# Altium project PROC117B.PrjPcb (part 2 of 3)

## Sheet PROC117B_Temp_Current_sensors_EPROM.SchDoc: TEMP_CURRENT_SENSORS_EEPROM
size 431 x 279 mm; Date: Not shown in title block; ApprovedBy: Not shown in title block; CheckedBy: Not shown in title block; Author: Not shown in title block; CompanyName: Not shown in title block; DrawnBy: Mistral; Engineer: Not shown in title block; Organization: Not shown in title block; Address1: Not shown in title block; Address2: Not shown in title block; Address3: Not shown in title block; Address4: Not shown in title block; DocumentNumber: 8; Revision: Use project parameter SCH_Rev; SheetNumber: 8; SheetTotal: 16; PageSetup: Record=PageOptions¦CenterHorizontal=True¦CenterVertical=True¦PrintScale=1.00¦XCorrection=1.00¦YCorrection=1.00¦PrintKind=0¦BorderSize=5000000¦LeftOffset=0¦BottomOffset=0¦Orientation=2¦PaperLength=1000¦PaperWidth=1000¦Scale=100¦PaperSource=15¦PrintQuality=600¦MediaType=1¦DitherType=10¦PaperKind=Letter¦PrintScaleMode=1
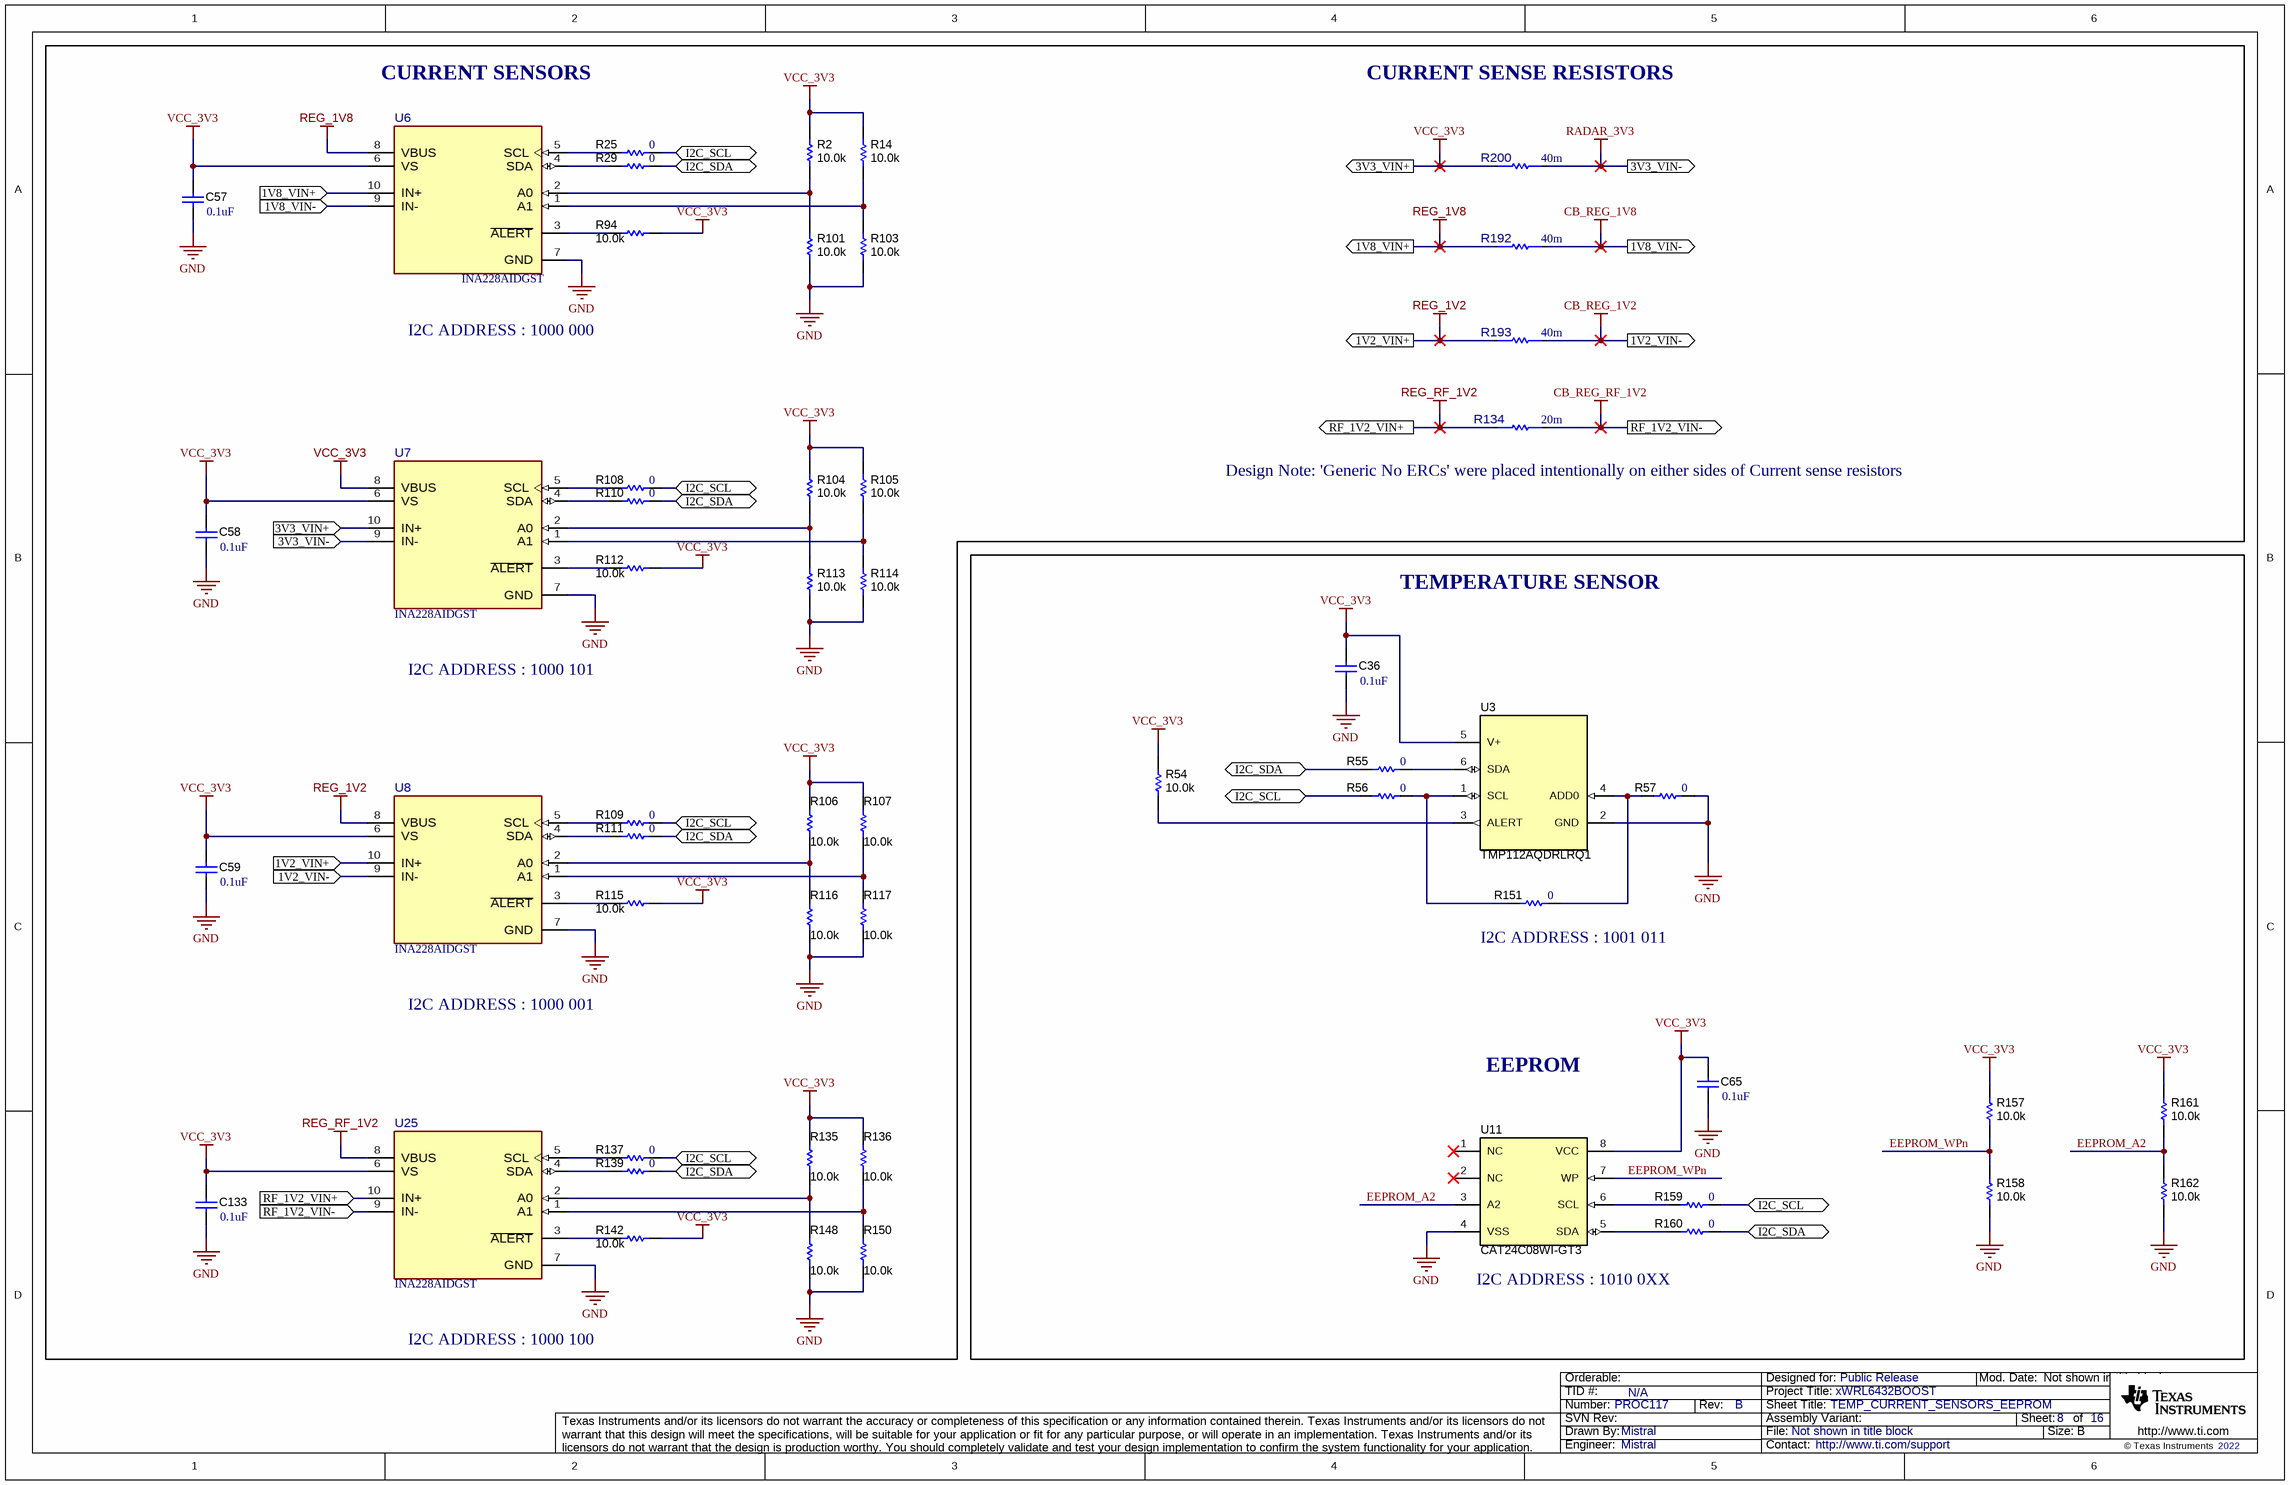
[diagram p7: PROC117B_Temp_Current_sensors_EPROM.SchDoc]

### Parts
C36  ValueDisplayed: 0.1uF  [0402]  (hidden comment: GCM155R71H104KE02D)
C57  ValueDisplayed: 0.1uF  [0402]  (hidden comment: GCM155R71H104KE02D)
C58  ValueDisplayed: 0.1uF  [0402]  (hidden comment: GCM155R71H104KE02D)
C59  ValueDisplayed: 0.1uF  [0402]  (hidden comment: GCM155R71H104KE02D)
C65  ValueDisplayed: 0.1uF  [0402]  (hidden comment: GCM155R71H104KE02D)
C133  ValueDisplayed: 0.1uF  [0402]  (hidden comment: GCM155R71H104KE02D)
R2  ValueDisplayed: 10.0k  [0402L]  (hidden comment: CRCW040210K0FKED)
R14  ValueDisplayed: 10.0k  [0402L]  (hidden comment: CRCW040210K0FKED)
R25  ValueDisplayed: 0  [0201]  (hidden comment: CRCW02010000Z0ED)
R29  ValueDisplayed: 0  [0201]  (hidden comment: CRCW02010000Z0ED)
R54  ValueDisplayed: 10.0k  [0402L]  (hidden comment: CRCW040210K0FKED)
R55  ValueDisplayed: 0  [0201]  (hidden comment: CRCW02010000Z0ED)
R56  ValueDisplayed: 0  [0201]  (hidden comment: CRCW02010000Z0ED)
R57  Res_ohm: 0  [0402]  (hidden comment: CRCW04020000Z0ED)
R94  ValueDisplayed: 10.0k  [0402L]  (hidden comment: CRCW040210K0FKED)
R101  ValueDisplayed: 10.0k  [0402L]  (hidden comment: CRCW040210K0FKED)
R103  ValueDisplayed: 10.0k  [0402L]  (hidden comment: CRCW040210K0FKED)
R104  ValueDisplayed: 10.0k  [0402L]  (hidden comment: CRCW040210K0FKED)
R105  ValueDisplayed: 10.0k  [0402L]  (hidden comment: CRCW040210K0FKED)
R106  ValueDisplayed: 10.0k  [0402L]  (hidden comment: CRCW040210K0FKED)
R107  ValueDisplayed: 10.0k  [0402L]  (hidden comment: CRCW040210K0FKED)
R108  ValueDisplayed: 0  [0201]  (hidden comment: CRCW02010000Z0ED)
R109  ValueDisplayed: 0  [0201]  (hidden comment: CRCW02010000Z0ED)
R110  ValueDisplayed: 0  [0201]  (hidden comment: CRCW02010000Z0ED)
R111  ValueDisplayed: 0  [0201]  (hidden comment: CRCW02010000Z0ED)
R112  ValueDisplayed: 10.0k  [0402L]  (hidden comment: CRCW040210K0FKED)
R113  ValueDisplayed: 10.0k  [0402L]  (hidden comment: CRCW040210K0FKED)
R114  ValueDisplayed: 10.0k  [0402L]  (hidden comment: CRCW040210K0FKED)
R115  ValueDisplayed: 10.0k  [0402L]  (hidden comment: CRCW040210K0FKED)
R116  ValueDisplayed: 10.0k  [0402L]  (hidden comment: CRCW040210K0FKED)
R117  ValueDisplayed: 10.0k  [0402L]  (hidden comment: CRCW040210K0FKED)
R134  value 20m  [FP-WSL1206R0200FEB_1206-MFG]  (hidden comment: WSL1206R0200FEB)
R135  ValueDisplayed: 10.0k  [0402L]  (hidden comment: CRCW040210K0FKED)
R136  ValueDisplayed: 10.0k  [0402L]  (hidden comment: CRCW040210K0FKED)
R137  ValueDisplayed: 0  [0201]  (hidden comment: CRCW02010000Z0ED)
R139  ValueDisplayed: 0  [0201]  (hidden comment: CRCW02010000Z0ED)
R142  ValueDisplayed: 10.0k  [0402L]  (hidden comment: CRCW040210K0FKED)
R148  ValueDisplayed: 10.0k  [0402L]  (hidden comment: CRCW040210K0FKED)
R150  ValueDisplayed: 10.0k  [0402L]  (hidden comment: CRCW040210K0FKED)
R151  Res_ohm: 0  [0402]  (hidden comment: CRCW04020000Z0ED)
R157  ValueDisplayed: 10.0k  [0402L]  (hidden comment: CRCW040210K0FKED)
R158  ValueDisplayed: 10.0k  [0402L]  (hidden comment: CRCW040210K0FKED)
R159  ValueDisplayed: 0  [0201]  (hidden comment: CRCW02010000Z0ED)
R160  ValueDisplayed: 0  [0201]  (hidden comment: CRCW02010000Z0ED)
R161  ValueDisplayed: 10.0k  [0402L]  (hidden comment: CRCW040210K0FKED)
R162  ValueDisplayed: 10.0k  [0402L]  (hidden comment: CRCW040210K0FKED)
R192  value 40m  [FP-WSL1206R0400FEB_1206-MFG]  (hidden comment: WSL1206R0400FEB)
R193  value 40m  [FP-WSL1206R0400FEB_1206-MFG]  (hidden comment: WSL1206R0400FEB)
R200  value 40m  [FP-WSL1206R0400FEB_1206-MFG]  (hidden comment: WSL1206R0400FEB)
U3  TMP112AQDRLRQ1  [DRL0006A]
U6  INA228AIDGST  [DGS0010A-MFG]
U7  INA228AIDGST  [DGS0010A-MFG]
U8  INA228AIDGST  [DGS0010A-MFG]
U11  CAT24C08WI-GT3  [SOIC-8]
U25  INA228AIDGST  [DGS0010A-MFG]

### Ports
1V2_VIN+ (in), 1V2_VIN+ (out), 1V2_VIN- (in), 1V2_VIN- (out), 1V8_VIN+ (in), 1V8_VIN+ (out), 1V8_VIN- (in), 1V8_VIN- (out), 3V3_VIN+ (in), 3V3_VIN+ (out), 3V3_VIN- (in), 3V3_VIN- (out), I2C_SCL (bidir), I2C_SDA (bidir), RF_1V2_VIN+ (in), RF_1V2_VIN+ (out), RF_1V2_VIN- (in), RF_1V2_VIN- (out)

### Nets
CB_REG_1V2: R193.2 U8.9(IN-) ; port 1V2_VIN-
CB_REG_1V8: R192.2 U6.9(IN-) ; port 1V8_VIN-
CB_REG_RF_1V2: R134.2 U25.9(IN-) ; port RF_1V2_VIN-
GND: C36.2 C57.2 C58.2 C59.2 C65.2 C133.2 R57.2 R101.1 R103.1 R113.1 R114.1 R116.1 R117.1 R148.1 R150.1 R158.1 R162.1 U3.2(GND) U6.7(GND) U7.7(GND) U8.7(GND) U11.4(VSS) U25.7(GND)
RADAR_3V3: R200.2 U7.9(IN-) ; port 3V3_VIN-
REG_1V2: R193.1 U8.8(VBUS) U8.10(IN+) ; port 1V2_VIN+
REG_1V8: R192.1 U6.8(VBUS) U6.10(IN+) ; port 1V8_VIN+
REG_RF_1V2: R134.1 U25.8(VBUS) U25.10(IN+) ; port RF_1V2_VIN+
VCC_3V3: C36.1 C57.1 C58.1 C59.1 C65.1 C133.1 R2.2 R14.2 R54.2 R94.1 R104.2 R105.2 R106.2 R107.2 R112.1 R115.1 R135.2 R136.2 R142.1 R157.2 R161.2 R200.1 U3.5(V+) U6.6(VS) U7.6(VS) U7.8(VBUS) U7.10(IN+) U8.6(VS) U11.8(VCC) U25.6(VS) ; port 3V3_VIN+
EEPROM_A2: R161.1 R162.2 U11.3(A2)
EEPROM_WPn: R157.1 R158.2 U11.7(WP)
I2C_SCL: R25.2 R56.1 R108.2 R109.2 R137.2 R159.2 ; port I2C_SCL
I2C_SDA: R29.2 R55.1 R110.2 R111.2 R139.2 R160.2 ; port I2C_SDA
NetR2_1: R2.1 R101.2 U6.2(A0)
NetR14_1: R14.1 R103.2 U6.1(A1)
NetR25_1: R25.1 U6.5(SCL)
NetR29_1: R29.1 U6.4(SDA)
NetR54_1: R54.1 U3.3(ALERT)
NetR55_2: R55.2 U3.6(SDA)
NetR56_2: R56.2 R151.1 U3.1(SCL)
NetR57_1: R57.1 R151.2 U3.4(ADD0)
NetR94_2: R94.2 U6.3(~{ALERT})
NetR104_1: R104.1 R113.2 U7.2(A0)
NetR105_1: R105.1 R114.2 U7.1(A1)
NetR106_1: R106.1 R116.2 U8.2(A0)
NetR107_1: R107.1 R117.2 U8.1(A1)
NetR108_1: R108.1 U7.5(SCL)
NetR109_1: R109.1 U8.5(SCL)
NetR110_1: R110.1 U7.4(SDA)
NetR111_1: R111.1 U8.4(SDA)
NetR112_2: R112.2 U7.3(~{ALERT})
NetR115_2: R115.2 U8.3(~{ALERT})
NetR135_1: R135.1 R148.2 U25.2(A0)
NetR136_1: R136.1 R150.2 U25.1(A1)
NetR137_1: R137.1 U25.5(SCL)
NetR139_1: R139.1 U25.4(SDA)
NetR142_2: R142.2 U25.3(~{ALERT})
NetR159_1: R159.1 U11.6(SCL)
NetR160_1: R160.1 U11.5(SDA)

Not connected (* = marked no-connect by the designer): U11 1(NC)* 2(NC)*

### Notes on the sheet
- CURRENT SENSORS
- CURRENT SENSE RESISTORS
- I2C ADDRESS : 1000 000
- (near R134) Design Note: 'Generic No ERCs' were placed intentionally on either sides of Current sense resistors
- TEMPERATURE SENSOR
- I2C ADDRESS : 1000 101
- (near R151) I2C ADDRESS : 1001 011
- I2C ADDRESS : 1000 001
- EEPROM
- I2C ADDRESS : 1010 0XX
- I2C ADDRESS : 1000 100

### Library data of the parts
C36 C57-C59 C65 C133 = CMP-0006356-2: CAP, CERM, 0.1 uF, 50 V, +/- 10%, X7R, AEC-Q200 Grade 1, 0402; Manufacturer: MuRata; TaMin_C: -55°C; Polarized: N; SizeAreaWB_mm2: 3; Value1: Unknown; U/M: EA; Value: 0.1uF; TaMax_C: 125°C; SizeZ_mm: 0.6; SizeX_mm: 1; SizeY_mm: 0.5; Value2: 50V; AEC Qualified: Y; Cap_F: 100nF; AEC Category: Q200
R2 R14 R54 R94 R101 R103-R107 R112-R117 R135 R136 R142 R148 R150 R157 R158 R161 R162 = CMP-0025958-3: RES, 10.0 k, 1%, 0.063 W, AEC-Q200 Grade 0, 0402; Manufacturer: Vishay-Dale; Power_W: 63mW; TempCo: 100 ppm/C; Value_Code: 10k0; Value: 10.0k; EIA_Code: E96; Res_ohm: 10k; SizeX_mm: 1; SizeY_mm: 0.5; SizeZ_mm: 0.6; Value2: 0.063W; AEC Qualified: Y; VDC_V: 50V; AEC Category: Q200; AEC Grade: 0
R25 R29 R55 R56 R108-R111 R137 R139 R159 R160 = CMP-0027008-4: RES, 0, 5%, 0.05 W, 0201; Manufacturer: Vishay-Dale; Power_W: 50mW; TempCo: ppm/C; Value_Code: 0000; Value: 0; EIA_Code: E24; SizeX_mm: 0.6; SizeY_mm: 0.3; SizeZ_mm: 0.26; Value2: 0.05W; SizeArea_mm2: 0.18; AEC Qualified: N; AEC Category: Q200
R57 = CMP-0026822-3: RES, 0, 5%, 0.063 W, AEC-Q200 Grade 0, 0402; Manufacturer: Vishay-Dale; Power_W: 63mW; TempCo: 200 ppm/C; Value_Code: 0000; Value: 0; EIA_Code: E24; SizeX_mm: 1; SizeY_mm: 0.5; SizeZ_mm: 0.6; Value2: 0.063W; CompType: Resistor; AEC Qualified: Y; VDC_V: 50V; AEC Category: Q200; INSTALLATION: DNP
R134 = CMP-0098430-1: Res Metal Strip 1206 0.02 Ohm 1% 1/4W ±75ppm/°C Molded SMD SMD T/R; Manufacturer: Vishay Dale; AEC Grade: Grade 0; AEC Qualified: Yes; Power_W: 250mW; SizeZ_mm: 0.889mm; Category 5C6A91606D4187Ad: Resistors; Category 7542B8484461Ae85: Passive Components; Category Cd01000Bfc2916C6: Single Components
R151 = CMP-0026822-3: RES, 0, 5%, 0.063 W, AEC-Q200 Grade 0, 0402; Manufacturer: Vishay-Dale; Power_W: 63mW; TempCo: 200 ppm/C; Value_Code: 0000; Value: 0; EIA_Code: E24; SizeX_mm: 1; SizeY_mm: 0.5; SizeZ_mm: 0.6; Value2: 0.063W; CompType: Resistor; AEC Qualified: Y; VDC_V: 50V; AEC Category: Q200
R192 R193 R200 = CMP-0098431-1: 40 mOhms ±1% 0.25W, 1/4W Chip Resistor Automotive AEC-Q200, Current Sense, Moisture Resistant, Pulse Withstanding Metal Element; Manufacturer: Vishay; AEC Grade: Grade 0; AEC Qualified: Yes; Power_W: 250mW; SizeZ_mm: 0.889mm; TempCo: 75ppm/°C
U3 = CMP-0067398-2: Automotive Grade, 1.4V-Capable +/-0.5degC Temperature Sensor with Alert Function and I2C/SMBus, DRL0006A (SOT-OTHER-6); Manufacturer: Texas Instruments; SizeZ_mm: 0.6; SizeX_mm: 1.6; SizeArea_mm2: 2.56; CompType: IC; U/M: EA; SizeAreaWB_mm2: 6.76
U6-U8 U25 = CMP-0098432-1: Current Sense Amplifier 1 Circuit 10-VSSOP; Manufacturer: Texas Instruments; SizeZ_mm: 1.1mm; AEC Qualified: No; Input Bias Current: 0.01uA; Input Offset Voltage: 1mV; Max Supply Voltage: 5.5V; Min Supply Voltage: 2.7V; Nominal Supply Current: 640uA; Number Of Channels: 1; Standoff Height: 0.05mm; TaMax_C: +125°C; TaMin_C: -40°C; TJmax_C: +150°C
U11 = CMP-0005309-2: IC, EEPROM, 8KBIT, 400KHZ, 8SOIC; Manufacturer: ON Semiconductor; SizeAreaWB_mm2: 55.131; SizeZ_mm: 1.75; SizeX_mm: 5.99; SizeY_mm: 4.9; SizeArea_mm2: 29.351

## Sheet PROC117B_QSPI_Flash_LVDS_Driver.SchDoc: QSPI_FLASH_LVDS_DRIVER
size 431 x 279 mm; Date: Not shown in title block; ApprovedBy: Not shown in title block; CheckedBy: Not shown in title block; Author: Not shown in title block; CompanyName: Not shown in title block; DrawnBy: Mistral; Engineer: Not shown in title block; Organization: Not shown in title block; Address1: Not shown in title block; Address2: Not shown in title block; Address3: Not shown in title block; Address4: Not shown in title block; DocumentNumber: 9; Revision: Use project parameter SCH_Rev; SheetNumber: 9; SheetTotal: 16; PageSetup: Record=PageOptions¦CenterHorizontal=True¦CenterVertical=True¦PrintScale=1.00¦XCorrection=1.00¦YCorrection=1.00¦PrintKind=0¦BorderSize=5000000¦LeftOffset=0¦BottomOffset=0¦Orientation=2¦PaperLength=1000¦PaperWidth=1000¦Scale=100¦PaperSource=15¦PrintQuality=600¦MediaType=1¦DitherType=10¦PaperKind=Letter¦PrintScaleMode=1
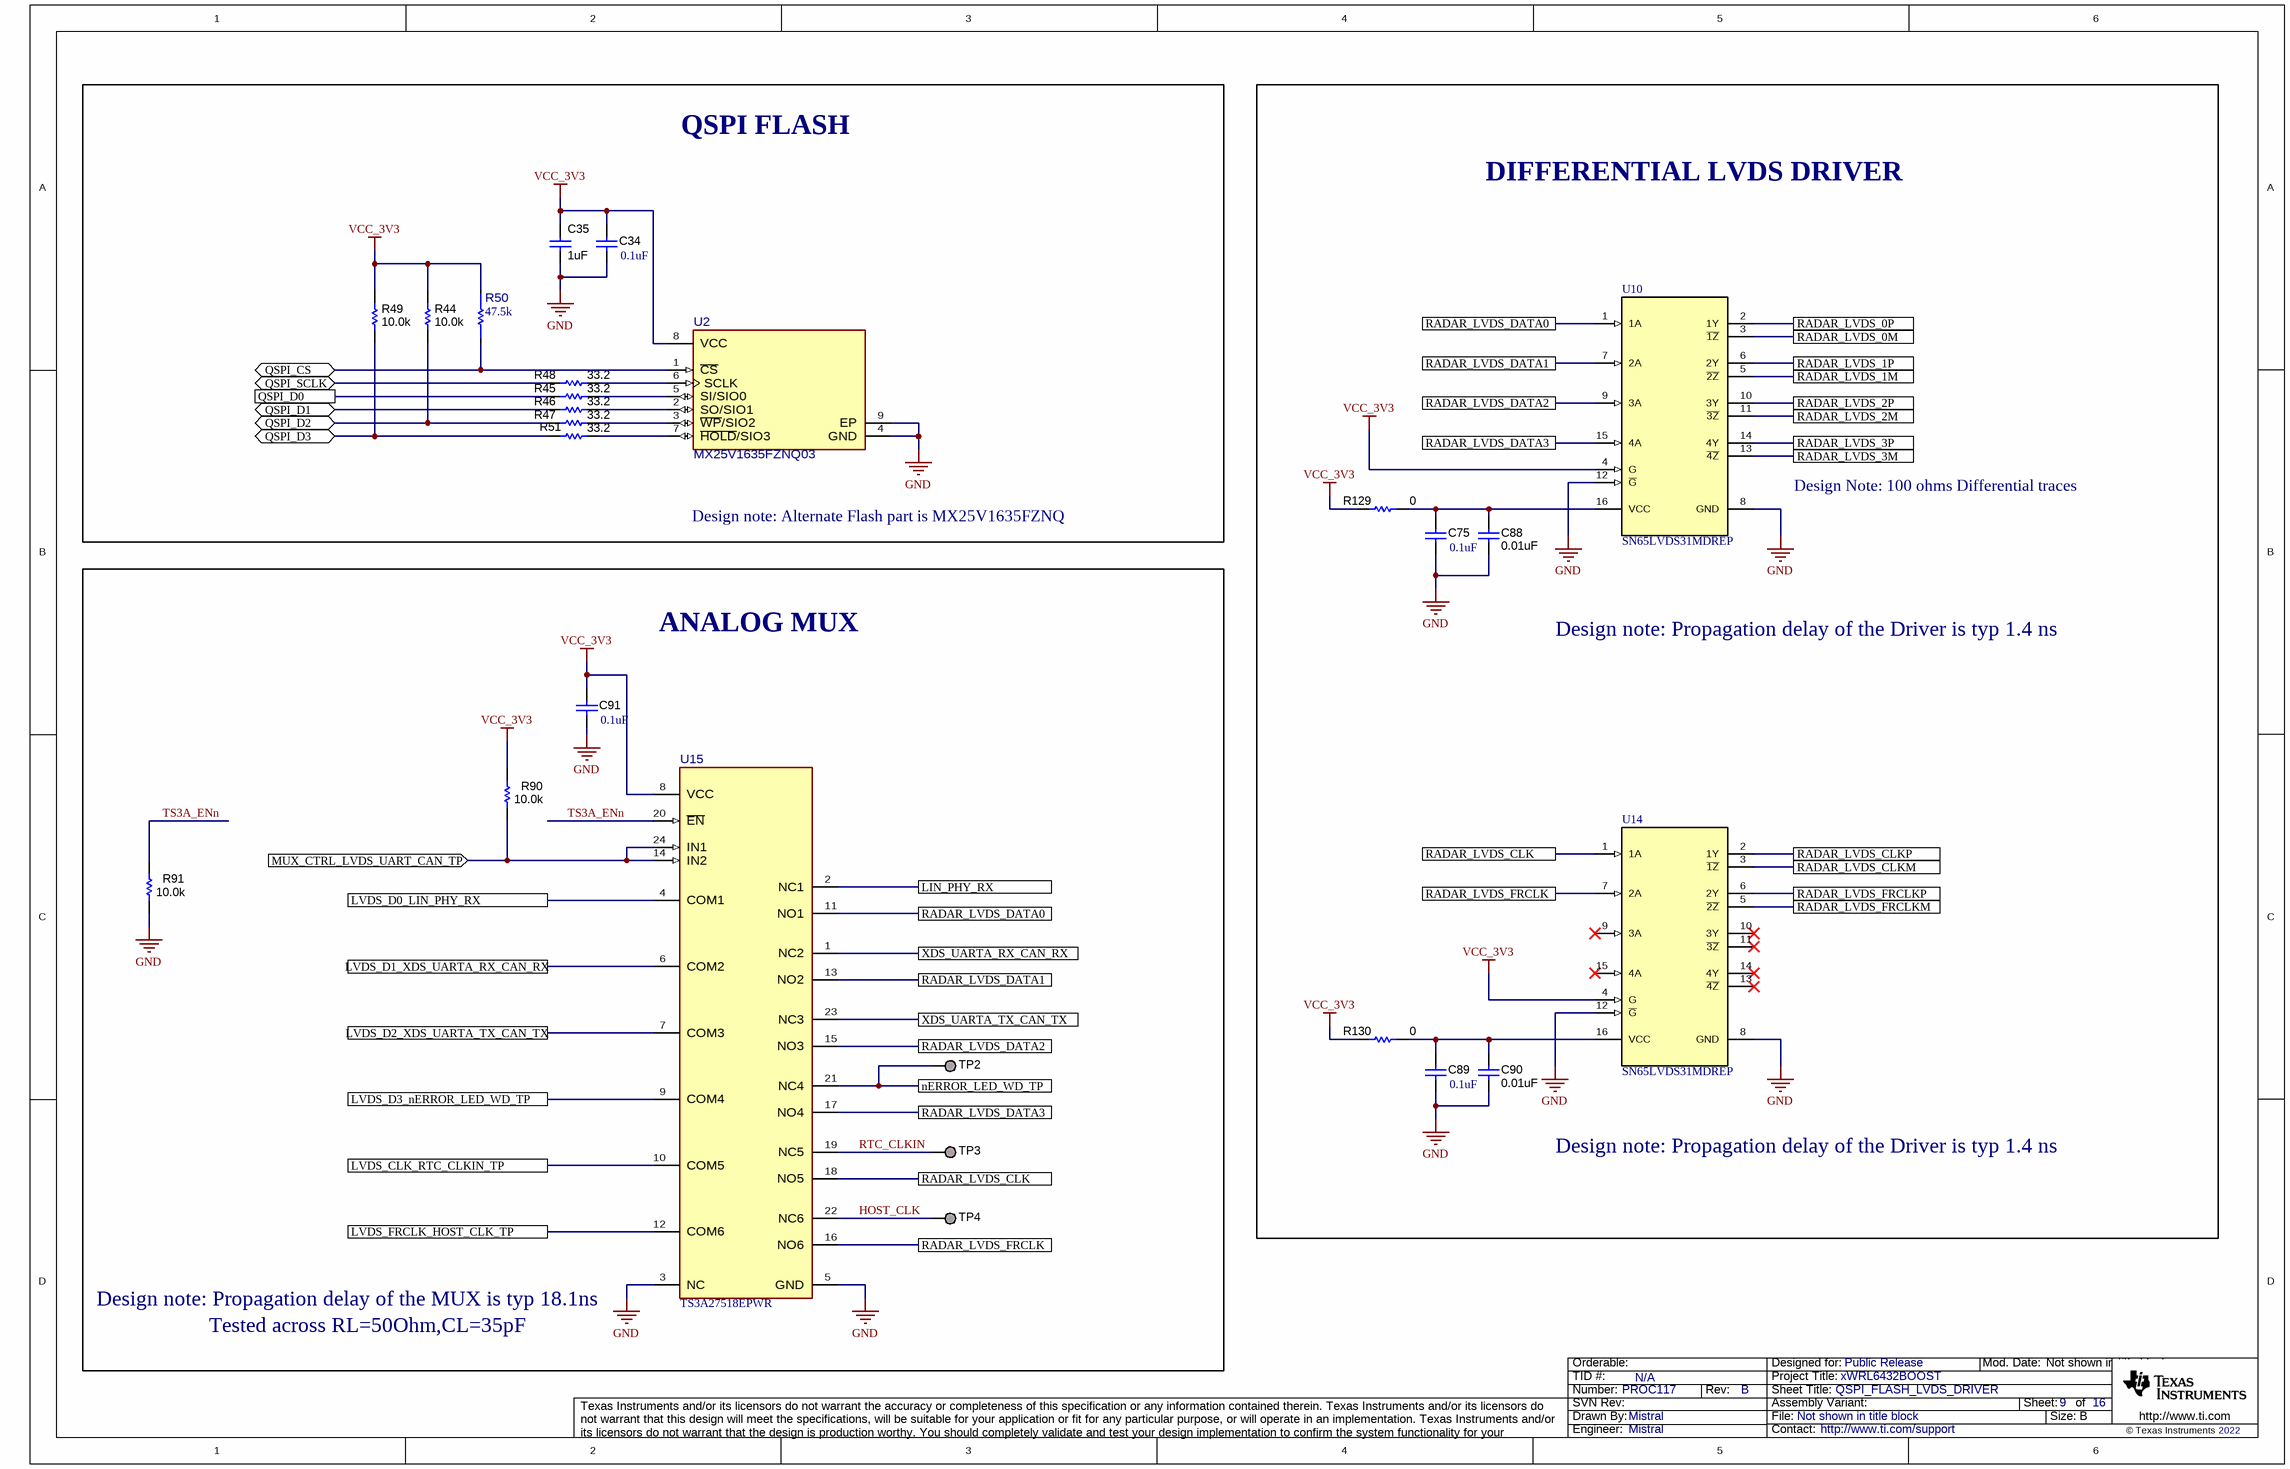
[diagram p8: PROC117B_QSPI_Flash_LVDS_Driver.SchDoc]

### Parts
C34  ValueDisplayed: 0.1uF  [0402]  (hidden comment: GCM155R71H104KE02D)
C35  ValueDisplayed: 1uF  [0603]  (hidden comment: GCM188R71C105KA64D)
C75  ValueDisplayed: 0.1uF  [0402]  (hidden comment: GCM155R71H104KE02D)
C88  ValueDisplayed: 0.01uF  [0402L]  (hidden comment: GCM155R71E103KA37D)
C89  ValueDisplayed: 0.1uF  [0402]  (hidden comment: GCM155R71H104KE02D)
C90  ValueDisplayed: 0.01uF  [0402L]  (hidden comment: GCM155R71E103KA37D)
C91  ValueDisplayed: 0.1uF  [0402]  (hidden comment: GCM155R71H104KE02D)
R44  ValueDisplayed: 10.0k  [0402L]  (hidden comment: CRCW040210K0FKED)
R45  ValueDisplayed: 33.2  [0201_Silk]  (hidden comment: CRCW020133R2FNED)
R46  ValueDisplayed: 33.2  [0201_Silk]  (hidden comment: CRCW020133R2FNED)
R47  ValueDisplayed: 33.2  [0201_Silk]  (hidden comment: CRCW020133R2FNED)
R48  ValueDisplayed: 33.2  [0201_Silk]  (hidden comment: CRCW020133R2FNED)
R49  ValueDisplayed: 10.0k  [0402L]  (hidden comment: CRCW040210K0FKED)
R50  Res_ohm: 47.5k  [FP-AC0402FR-0747K5L_0402-MFG]  (hidden comment: AC0402FR-0747K5L)
R51  ValueDisplayed: 33.2  [0201_Silk]  (hidden comment: CRCW020133R2FNED)
R90  ValueDisplayed: 10.0k  [0402L]  (hidden comment: CRCW040210K0FKED)
R91  ValueDisplayed: 10.0k  [0402L]  (hidden comment: CRCW040210K0FKED)
R129  ValueDisplayed: 0  [0603]  (hidden comment: MCT06030Z0000ZP500)
R130  ValueDisplayed: 0  [0603]  (hidden comment: MCT06030Z0000ZP500)
TP2  TESTPOINT  [TP_25MIL-SMT]  (value not drawn)  (no BOM)
TP3  TESTPOINT  [TP_25MIL-SMT]  (value not drawn)  (no BOM)
TP4  TESTPOINT  [TP_25MIL-SMT]  (value not drawn)  (no BOM)
U2  MX25V1635FZNQ03  [FP-MX25V1635FZNQ03_WSON8-MFG]
U10  SN65LVDS31MDREP  [D0016A_N]
U14  SN65LVDS31MDREP  [D0016A_N]
U15  TS3A27518EPWR  [PW0024A-MFG]

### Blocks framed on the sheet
QSPI FLASH: C34 C35 R44-R51 U2
DIFFERENTIAL LVDS DRIVER: C75 C88-C90 R129 R130 U10 U14
ANALOG MUX: C91 R90 R91 TP2-TP4 U15

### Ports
LIN_PHY_RX, LVDS_CLK_RTC_CLKIN_TP, LVDS_D0_LIN_PHY_RX, LVDS_D1_XDS_UARTA_RX_CAN_RX, LVDS_D2_XDS_UARTA_TX_CAN_TX, LVDS_D3_nERROR_LED_WD_TP, LVDS_FRCLK_HOST_CLK_TP, MUX_CTRL_LVDS_UART_CAN_TP (in), nERROR_LED_WD_TP, QSPI_CS (bidir), QSPI_D0, QSPI_D1 (bidir), QSPI_D2 (bidir), QSPI_D3 (bidir), QSPI_SCLK (bidir), RADAR_LVDS_0M, RADAR_LVDS_0P, RADAR_LVDS_1M, RADAR_LVDS_1P, RADAR_LVDS_2M, RADAR_LVDS_2P, RADAR_LVDS_3M, RADAR_LVDS_3P, RADAR_LVDS_CLK, RADAR_LVDS_CLKM, RADAR_LVDS_CLKP, RADAR_LVDS_DATA0, RADAR_LVDS_DATA1, RADAR_LVDS_DATA2, RADAR_LVDS_DATA3, RADAR_LVDS_FRCLK, RADAR_LVDS_FRCLKM, RADAR_LVDS_FRCLKP, XDS_UARTA_RX_CAN_RX, XDS_UARTA_TX_CAN_TX

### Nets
GND: C34.2 C35.1 C75.2 C88.2 C89.2 C90.2 C91.2 R91.2 U2.4(GND) U2.9(EP) U10.8(GND) U10.12(~{G}) U14.8(GND) U14.12(~{G}) U15.3(NC) U15.5(GND)
VCC_3V3: C34.1 C35.2 C91.1 R44.2 R49.2 R50.1 R90.1 R129.1 R130.1 U2.8(VCC) U10.4(G) U14.4(G) U15.8(VCC)
HOST_CLK: TP4.1 U15.22(NC6)
LIN_PHY_RX: U15.2(NC1) ; port LIN_PHY_RX
LVDS_CLK_RTC_CLKIN_TP: U15.10(COM5) ; port LVDS_CLK_RTC_CLKIN_TP
LVDS_D0_LIN_PHY_RX: U15.4(COM1) ; port LVDS_D0_LIN_PHY_RX
LVDS_D1_XDS_UARTA_RX_CAN_RX: U15.6(COM2) ; port LVDS_D1_XDS_UARTA_RX_CAN_RX
LVDS_D2_XDS_UARTA_TX_CAN_TX: U15.7(COM3) ; port LVDS_D2_XDS_UARTA_TX_CAN_TX
LVDS_D3_nERROR_LED_WD_TP: U15.9(COM4) ; port LVDS_D3_nERROR_LED_WD_TP
LVDS_FRCLK_HOST_CLK_TP: U15.12(COM6) ; port LVDS_FRCLK_HOST_CLK_TP
MUX_CTRL_LVDS_UART_CAN_TP: R90.2 U15.14(IN2) U15.24(IN1) ; port MUX_CTRL_LVDS_UART_CAN_TP
nERROR_LED_WD_TP: TP2.1 U15.21(NC4) ; port nERROR_LED_WD_TP
QSPI_CS: R50.2 U2.1(~{CS}) ; port QSPI_CS
QSPI_D0: R45.2 ; port QSPI_D0
QSPI_D1: R46.1 ; port QSPI_D1
QSPI_D2: R44.1 R47.1 ; port QSPI_D2
QSPI_D3: R49.1 R51.2 ; port QSPI_D3
QSPI_SCLK: R48.2 ; port QSPI_SCLK
RADAR_LVDS_0M: U10.3(~{1Z}) ; port RADAR_LVDS_0M
RADAR_LVDS_0P: U10.2(1Y) ; port RADAR_LVDS_0P
RADAR_LVDS_1M: U10.5(~{2Z}) ; port RADAR_LVDS_1M
RADAR_LVDS_1P: U10.6(2Y) ; port RADAR_LVDS_1P
RADAR_LVDS_2M: U10.11(~{3Z}) ; port RADAR_LVDS_2M
RADAR_LVDS_2P: U10.10(3Y) ; port RADAR_LVDS_2P
RADAR_LVDS_3M: U10.13(~{4Z}) ; port RADAR_LVDS_3M
RADAR_LVDS_3P: U10.14(4Y) ; port RADAR_LVDS_3P
RADAR_LVDS_CLK: U14.1(1A) U15.18(NO5) ; port RADAR_LVDS_CLK
RADAR_LVDS_CLKM: U14.3(~{1Z}) ; port RADAR_LVDS_CLKM
RADAR_LVDS_CLKP: U14.2(1Y) ; port RADAR_LVDS_CLKP
RADAR_LVDS_DATA0: U10.1(1A) U15.11(NO1) ; port RADAR_LVDS_DATA0
RADAR_LVDS_DATA1: U10.7(2A) U15.13(NO2) ; port RADAR_LVDS_DATA1
RADAR_LVDS_DATA2: U10.9(3A) U15.15(NO3) ; port RADAR_LVDS_DATA2
RADAR_LVDS_DATA3: U10.15(4A) U15.17(NO4) ; port RADAR_LVDS_DATA3
RADAR_LVDS_FRCLK: U14.7(2A) U15.16(NO6) ; port RADAR_LVDS_FRCLK
RADAR_LVDS_FRCLKM: U14.5(~{2Z}) ; port RADAR_LVDS_FRCLKM
RADAR_LVDS_FRCLKP: U14.6(2Y) ; port RADAR_LVDS_FRCLKP
RTC_CLKIN: TP3.1 U15.19(NC5)
TS3A_ENn: R91.1 U15.20(~{EN})
XDS_UARTA_RX_CAN_RX: U15.1(NC2) ; port XDS_UARTA_RX_CAN_RX
XDS_UARTA_TX_CAN_TX: U15.23(NC3) ; port XDS_UARTA_TX_CAN_TX
NetC75_1: C75.1 C88.1 R129.2 U10.16(VCC)
NetC89_1: C89.1 C90.1 R130.2 U14.16(VCC)
NetR45_1: R45.1 U2.5(SI/SIO0)
NetR46_2: R46.2 U2.2(SO/SIO1)
NetR47_2: R47.2 U2.3(~{WP}/SIO2)
NetR48_1: R48.1 U2.6(SCLK)
NetR51_1: R51.1 U2.7(~{HOLD}/SIO3)

Not connected (* = marked no-connect by the designer): U14 9(3A)* 10(3Y)* 11(~{3Z})* 13(~{4Z})* 14(4Y)* 15(4A)*

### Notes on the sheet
- Design Note: 100 ohms Differential traces
- Design note: Alternate Flash part is MX25V1635FZNQ
- Design note: Propagation delay of the Driver is typ 1.4 ns
- (near U15) Design note: Propagation delay of the MUX is typ 18.1ns
- Tested across RL=50Ohm,CL=35pF

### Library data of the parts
C34 C75 C89 C91 = CMP-0006356-2: as C36 on sheet PROC117B_Temp_Current_sensors_EPROM
C35 = CMP-0007136-5: CAP, CERM, 1 uF, 16 V, +/- 10%, X7R, AEC-Q200 Grade 1, 0603; Manufacturer: MuRata; TaMin_C: -55°C; Polarized: N; SizeAreaWB_mm2: 4.68; Value1: Unknown; U/M: EA; Value: 1uF; TaMax_C: 125°C; SizeZ_mm: 1; SizeX_mm: 1.6; SizeY_mm: 0.8; Value2: 16V; SizeArea_mm2: 1.28; CompType: Capacitor; AEC Qualified: Y; Cap_F: 1µF; AEC Category: Q200
C88 C90 = CMP-0006352-2: CAP, CERM, 0.01 uF, 25 V, +/- 10%, X7R, 0402; Manufacturer: MuRata; TaMin_C: -55°C; Polarized: N; SizeAreaWB_mm2: 3; Value1: Unknown; U/M: EA; Value: 0.01uF; TaMax_C: 125°C; SizeZ_mm: 0.6; SizeX_mm: 1; SizeY_mm: 0.5; Cap_Case: 0402; Value2: 25V; CompType: Capacitor; Cap_F: 10nF; AEC Category: Q200
R44 R49 R90 R91 = CMP-0025958-3: as R2 on sheet PROC117B_Temp_Current_sensors_EPROM
R45-R48 R51 = CMP-0027275-3: RES, 33.2, 1%, 0.05 W, 0201; Manufacturer: Vishay-Dale; Power_W: 50mW; TempCo: 200 ppm/C; Value_Code: 33R2; Value: 33.2; EIA_Code: E96; SizeX_mm: 0.6; SizeY_mm: 0.3; SizeZ_mm: 0.26; Value2: 0.05W; SizeArea_mm2: 0.18; AEC Qualified: N; AEC Category: Q200
R50 = CMP-0095013-1: Res Thick Film 0402 47.5K Ohm 1% 1/16W ±100ppm/°C Molded SMD Paper T/R; Manufacturer: Yageo; VDC_V: 50V; SizeZ_mm: 0.37mm; AEC Grade: Grade 0; Power_W: 62.5mW; AEC Qualified: Yes
R129 R130 = CMP-0025884-3: RES, 0, 5%, 0.125 W, 0603; Manufacturer: Vishay/Beyschlag; Power_W: 125mW; TempCo: ppm/C; Value_Code: 0000; U/M: EA; Value: 0; EIA_Code: E24; SizeX_mm: 1.6; SizeY_mm: 0.8; SizeZ_mm: 1; Value2: 0.125W; SizeArea_mm2: 1.28; CompType: Resistor; AEC Qualified: N; AEC Category: Q200; INSTALATION: DNP
TP2-TP4 = CMP-0078143-3: TEST POINT.  No entry in BOM.
U2 = CMP-0093403-2: NOR Flash 16Mbit 16M x 1/8M x 2/4M x 4 Serial-SPI 3.3V 8-Pin WSON; Manufacturer: Macronix; TaMax_C: +85°C; AEC Qualified: No; Interface: SPI; Max Supply Voltage: 3.6V; TaMin_C: -40°C; Min Supply Voltage: 2.3V; Memory Type: FLASH,NOR; SizeZ_mm: 0.8mm; Memory Size: 16Mbits; Frequency_Fixed: 80MHz
U10 U14 = CMP-0029468-1: 400 Mbps Enhanced Product Quad LVDS Transmitter with LVTTL Input and Output, 4 Tx and 0 Rx, -55 to +125 degC, 16-pin SOIC (D), Green (RoHS & no Sb/Br); Manufacturer: Texas Instruments; ESD HBM(kV): 8; Signaling Rate(Mbps): 400; ICC(Max)(mA): 35; No. of Tx: 4; SubFamily: LVDS PHY (<800Mbps)
U15 = CMP-0092155-1: 3.3-V, 2:1 (SPDT), 6-channel analog multiplexer with 1.8-V compatible control inputs 24-TSSOP -40 to 85; Manufacturer: Texas Instruments; Max Supply Voltage: 3.6V; -3Db Bandwith: 240MHz; Standoff Height: 0.05mm; Category 9E37533Dafe045F0: Logic, Standard; SizeZ_mm: 1.2mm; On State Resistance: 4.4Ω; Category Aef863F29A99753F: Switches; AEC Qualified: No; Category 9E07530Daf1645C0: Semiconductors and Actives; Min Supply Voltage: 1.65V; Nominal Supply Current: 0.01-0.04uA; PositionCount: 6

## Sheet PROC117B_Analog_Mux_SOP_Ctrl.SchDoc: ANALOG_MUX_SOP_CTRL
size 431 x 279 mm; Date: Not shown in title block; ApprovedBy: Not shown in title block; CheckedBy: Not shown in title block; Author: Not shown in title block; CompanyName: Not shown in title block; DrawnBy: Mistral; Engineer: Not shown in title block; Organization: Not shown in title block; Address1: Not shown in title block; Address2: Not shown in title block; Address3: Not shown in title block; Address4: Not shown in title block; DocumentNumber: 10; Revision: Use project parameter SCH_Rev; SheetNumber: 10; SheetTotal: 16; PageSetup: Record=PageOptions¦CenterHorizontal=True¦CenterVertical=True¦PrintScale=1.00¦XCorrection=1.00¦YCorrection=1.00¦PrintKind=0¦BorderSize=5000000¦LeftOffset=0¦BottomOffset=0¦Orientation=2¦PaperLength=1000¦PaperWidth=1000¦Scale=100¦PaperSource=15¦PrintQuality=600¦MediaType=1¦DitherType=10¦PaperKind=Letter¦PrintScaleMode=1
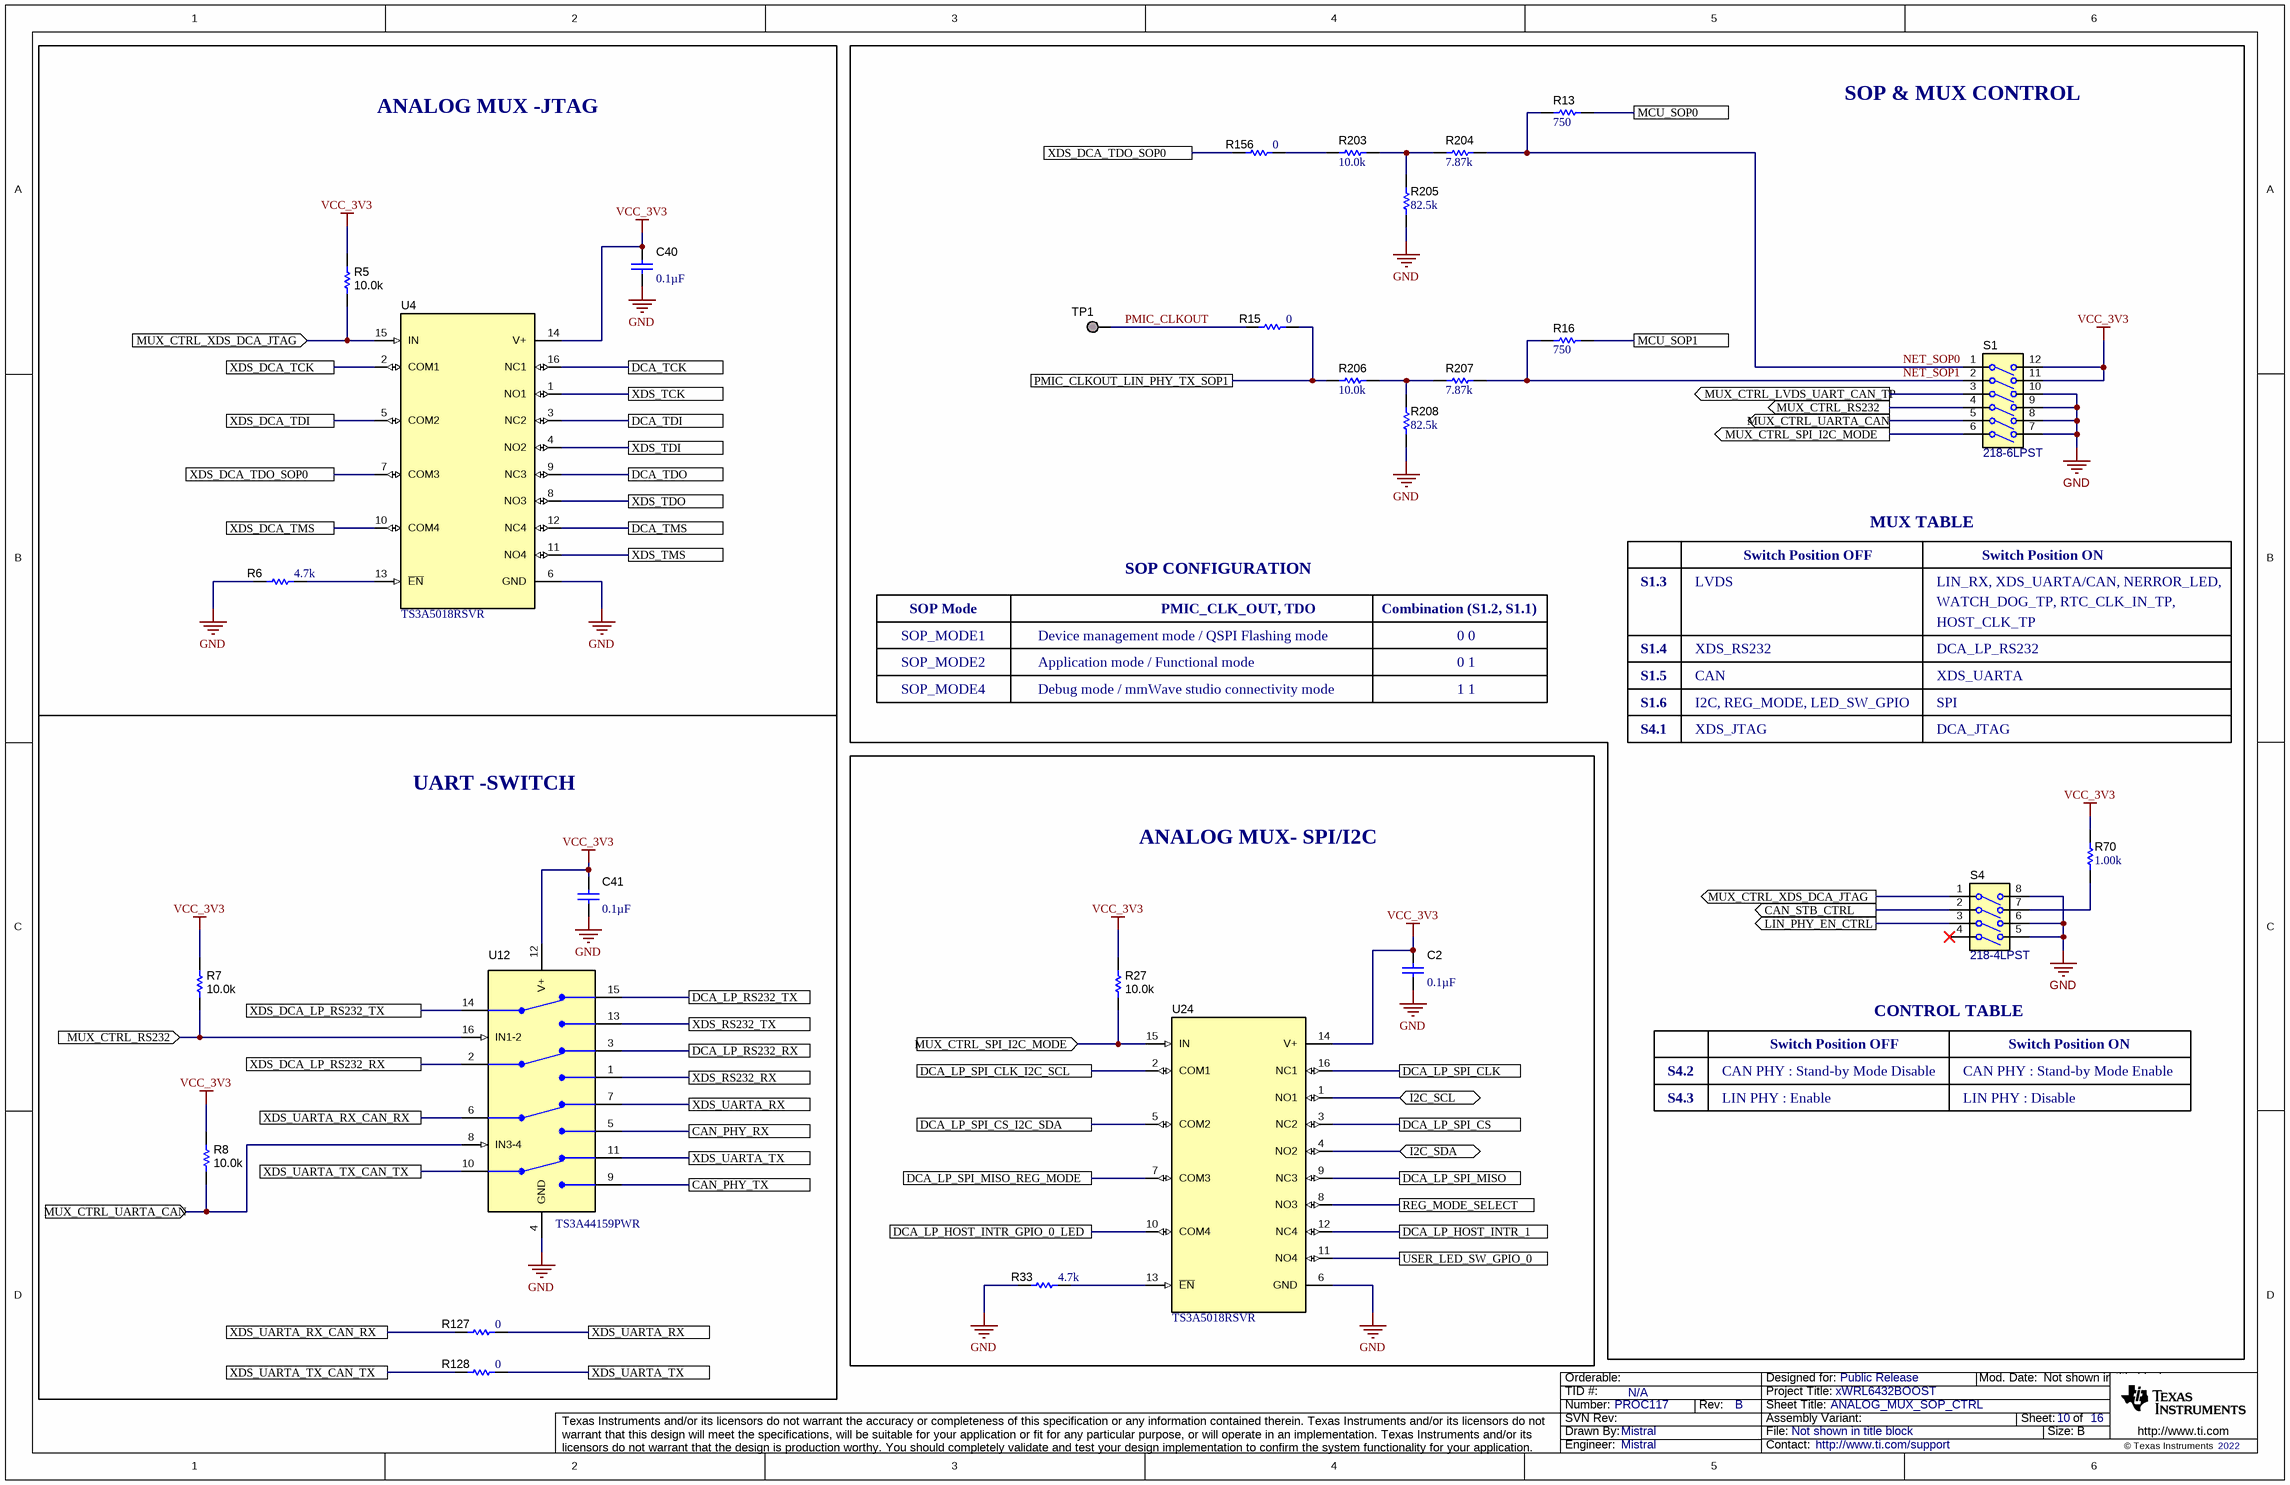
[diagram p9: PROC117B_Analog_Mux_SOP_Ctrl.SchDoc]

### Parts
C2  ValueDisplayed: 0.1µF  [0402]  (hidden comment: C0402C104K8RACTU)
C40  ValueDisplayed: 0.1µF  [0402]  (hidden comment: C0402C104K8RACTU)
C41  ValueDisplayed: 0.1µF  [0402]  (hidden comment: C0402C104K8RACTU)
R5  ValueDisplayed: 10.0k  [0402L]  (hidden comment: CRCW040210K0FKED)
R6  ValueDisplayed: 4.7k  [0402]  (hidden comment: CRCW04024K70JNED)
R7  ValueDisplayed: 10.0k  [0402L]  (hidden comment: CRCW040210K0FKED)
R8  ValueDisplayed: 10.0k  [0402L]  (hidden comment: CRCW040210K0FKED)
R13  ValueDisplayed: 750  [0402L]  (hidden comment: CRCW0402750RFKED)
R15  ValueDisplayed: 0  [0402L]  (hidden comment: ERJ-2GE0R00X)
R16  ValueDisplayed: 750  [0402L]  (hidden comment: CRCW0402750RFKED)
R27  ValueDisplayed: 10.0k  [0402L]  (hidden comment: CRCW040210K0FKED)
R33  ValueDisplayed: 4.7k  [0402]  (hidden comment: CRCW04024K70JNED)
R70  ValueDisplayed: 1.00k  [0402L]  (hidden comment: CRCW04021K00FKED)
R127  ValueDisplayed: 0  [0402]  (hidden comment: ERJ-2GE0R00X)
R128  ValueDisplayed: 0  [0402]  (hidden comment: ERJ-2GE0R00X)
R156  ValueDisplayed: 0  [0402L]  (hidden comment: ERJ-2GE0R00X)
R203  ValueDisplayed: 10.0k  [0402L]  (hidden comment: CRCW040210K0FKED)
R204  ValueDisplayed: 7.87k  [0402L]  (hidden comment: CRCW04027K87FKED)
R205  ValueDisplayed: 82.5k  [0402L]  (hidden comment: CRCW040282K5FKED)
R206  ValueDisplayed: 10.0k  [0402L]  (hidden comment: CRCW040210K0FKED)
R207  ValueDisplayed: 7.87k  [0402L]  (hidden comment: CRCW04027K87FKED)
R208  ValueDisplayed: 82.5k  [0402L]  (hidden comment: CRCW040282K5FKED)
S1  218-6LPST  [SW_218-6LPST]
S4  218-4LPST  [SW_218-4LPST]
TP1  TESTPOINT  [TP_VIA_060RND040]  (value not drawn)  (no BOM)
U4  TS3A5018RSVR  [RSV0016A]
U12  TS3A44159PWR  [PW0016A_N]
U24  TS3A5018RSVR  [RSV0016A]

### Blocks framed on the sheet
SOP & MUX CONTROL: R13 R15 R16 R70 R156 R203-R208 S1 S4 TP1
ANALOG MUX- SPI/I2C: C2 R27 R33 U24

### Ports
CAN_PHY_RX, CAN_PHY_TX, CAN_STB_CTRL (out), DCA_LP_HOST_INTR_1, DCA_LP_HOST_INTR_GPIO_0_LED, DCA_LP_RS232_RX, DCA_LP_RS232_TX, DCA_LP_SPI_CLK, DCA_LP_SPI_CLK_I2C_SCL, DCA_LP_SPI_CS, DCA_LP_SPI_CS_I2C_SDA, DCA_LP_SPI_MISO, DCA_LP_SPI_MISO_REG_MODE, DCA_TCK, DCA_TDI, DCA_TDO, DCA_TMS, I2C_SCL (bidir), I2C_SDA (bidir), LIN_PHY_EN_CTRL (out), MCU_SOP0, MCU_SOP1, MUX_CTRL_LVDS_UART_CAN_TP (out), MUX_CTRL_RS232 (in), MUX_CTRL_RS232 (out), MUX_CTRL_SPI_I2C_MODE (in), MUX_CTRL_SPI_I2C_MODE (out), MUX_CTRL_UARTA_CAN (in), MUX_CTRL_UARTA_CAN (out), MUX_CTRL_XDS_DCA_JTAG (in), MUX_CTRL_XDS_DCA_JTAG (out), PMIC_CLKOUT_LIN_PHY_TX_SOP1, REG_MODE_SELECT, USER_LED_SW_GPIO_0, XDS_DCA_LP_RS232_RX, XDS_DCA_LP_RS232_TX, XDS_DCA_TCK, XDS_DCA_TDI, XDS_DCA_TDO_SOP0, XDS_DCA_TMS, XDS_RS232_RX, XDS_RS232_TX, XDS_TCK, XDS_TDI, XDS_TDO, XDS_TMS, XDS_UARTA_RX, XDS_UARTA_RX_CAN_RX, XDS_UARTA_TX, XDS_UARTA_TX_CAN_TX

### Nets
GND: C2.2 C40.2 C41.2 R6.1 R33.1 R205.1 R208.1 S1.7(6A) S1.8(5A) S1.9(4A) S1.10(3A) S4.5(B4) S4.6(B3) S4.8(B1) U4.6(GND) U12.4(GND) U24.6(GND)
VCC_3V3: C2.1 C40.1 C41.1 R5.2 R7.2 R8.2 R27.2 R70.2 S1.11(2A) S1.12(1A) U4.14(V+) U12.12(V+) U24.14(V+)
CAN_PHY_RX: U12.5(NO3) ; port CAN_PHY_RX
CAN_PHY_TX: U12.9(NO4) ; port CAN_PHY_TX
CAN_STB_CTRL: S4.2(A2) ; port CAN_STB_CTRL
DCA_LP_HOST_INTR_1: U24.12(NC4) ; port DCA_LP_HOST_INTR_1
DCA_LP_HOST_INTR_GPIO_0_LED: U24.10(COM4) ; port DCA_LP_HOST_INTR_GPIO_0_LED
DCA_LP_RS232_RX: U12.3(NC2) ; port DCA_LP_RS232_RX
DCA_LP_RS232_TX: U12.15(NC1) ; port DCA_LP_RS232_TX
DCA_LP_SPI_CLK: U24.16(NC1) ; port DCA_LP_SPI_CLK
DCA_LP_SPI_CLK_I2C_SCL: U24.2(COM1) ; port DCA_LP_SPI_CLK_I2C_SCL
DCA_LP_SPI_CS: U24.3(NC2) ; port DCA_LP_SPI_CS
DCA_LP_SPI_CS_I2C_SDA: U24.5(COM2) ; port DCA_LP_SPI_CS_I2C_SDA
DCA_LP_SPI_MISO: U24.9(NC3) ; port DCA_LP_SPI_MISO
DCA_LP_SPI_MISO_REG_MODE: U24.7(COM3) ; port DCA_LP_SPI_MISO_REG_MODE
DCA_TCK: U4.16(NC1) ; port DCA_TCK
DCA_TDI: U4.3(NC2) ; port DCA_TDI
DCA_TDO: U4.9(NC3) ; port DCA_TDO
DCA_TMS: U4.12(NC4) ; port DCA_TMS
I2C_SCL: U24.1(NO1) ; port I2C_SCL
I2C_SDA: U24.4(NO2) ; port I2C_SDA
LIN_PHY_EN_CTRL: S4.3(A3) ; port LIN_PHY_EN_CTRL
MCU_SOP0: R13.1 ; port MCU_SOP0
MCU_SOP1: R16.1 ; port MCU_SOP1
MUX_CTRL_LVDS_UART_CAN_TP: S1.3 ; port MUX_CTRL_LVDS_UART_CAN_TP
MUX_CTRL_RS232: R7.1 S1.4 U12.16(IN1-2) ; port MUX_CTRL_RS232
MUX_CTRL_SPI_I2C_MODE: R27.1 S1.6 U24.15(IN) ; port MUX_CTRL_SPI_I2C_MODE
MUX_CTRL_UARTA_CAN: R8.1 S1.5 U12.8(IN3-4) ; port MUX_CTRL_UARTA_CAN
MUX_CTRL_XDS_DCA_JTAG: R5.1 S4.1(A1) U4.15(IN) ; port MUX_CTRL_XDS_DCA_JTAG
NET_SOP0: R13.2 R204.2 S1.1
NET_SOP1: R16.2 R207.2 S1.2
PMIC_CLKOUT: R15.2 TP1.1
PMIC_CLKOUT_LIN_PHY_TX_SOP1: R15.1 R206.1 ; port PMIC_CLKOUT_LIN_PHY_TX_SOP1
REG_MODE_SELECT: U24.8(NO3) ; port REG_MODE_SELECT
USER_LED_SW_GPIO_0: U24.11(NO4) ; port USER_LED_SW_GPIO_0
XDS_DCA_LP_RS232_RX: U12.2(COM2) ; port XDS_DCA_LP_RS232_RX
XDS_DCA_LP_RS232_TX: U12.14(COM1) ; port XDS_DCA_LP_RS232_TX
XDS_DCA_TCK: U4.2(COM1) ; port XDS_DCA_TCK
XDS_DCA_TDI: U4.5(COM2) ; port XDS_DCA_TDI
XDS_DCA_TDO_SOP0: R156.2 U4.7(COM3) ; port XDS_DCA_TDO_SOP0
XDS_DCA_TMS: U4.10(COM4) ; port XDS_DCA_TMS
XDS_RS232_RX: U12.1(NO2) ; port XDS_RS232_RX
XDS_RS232_TX: U12.13(NO1) ; port XDS_RS232_TX
XDS_TCK: U4.1(NO1) ; port XDS_TCK
XDS_TDI: U4.4(NO2) ; port XDS_TDI
XDS_TDO: U4.8(NO3) ; port XDS_TDO
XDS_TMS: U4.11(NO4) ; port XDS_TMS
XDS_UARTA_RX: R127.2 U12.7(NC3) ; port XDS_UARTA_RX
XDS_UARTA_RX_CAN_RX: R127.1 U12.6(COM3) ; port XDS_UARTA_RX_CAN_RX
XDS_UARTA_TX: R128.2 U12.11(NC4) ; port XDS_UARTA_TX
XDS_UARTA_TX_CAN_TX: R128.1 U12.10(COM4) ; port XDS_UARTA_TX_CAN_TX
NetR6_2: R6.2 U4.13(~{EN})
NetR33_2: R33.2 U24.13(~{EN})
NetR70_1: R70.1 S4.7(B2)
NetR156_1: R156.1 R203.1
NetR203_2: R203.2 R204.1 R205.2
NetR206_2: R206.2 R207.1 R208.2

Not connected (* = marked no-connect by the designer): S4 4(A4)*

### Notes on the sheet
- ANALOG MUX -JTAG
- SOP CONFIGURATION
- Switch Position OFF
- MUX TABLE
- Switch Position ON
- SOP_MODE1
- SOP Mode
- Device management mode / QSPI Flashing mode
- PMIC_CLK_OUT, TDO
- Combination (S1.2, S1.1)
- 0 0
- S1.3
- LVDS
- LIN_RX, XDS_UARTA/CAN, NERROR_LED,
- WATCH_DOG_TP, RTC_CLK_IN_TP,
- HOST_CLK_TP
- SOP_MODE2
- SOP_MODE4
- Application mode / Functional mode
- Debug mode / mmWave studio connectivity mode
- 0 1
- 1 1
- S1.4
- S1.5
- S1.6
- XDS_RS232
- I2C, REG_MODE, LED_SW_GPIO
- CAN
- DCA_LP_RS232
- SPI
- XDS_UARTA
- S4.1
- XDS_JTAG
- DCA_JTAG
- UART -SWITCH
- CONTROL TABLE
- S4.2
- S4.3
- CAN PHY : Stand-by Mode Disable
- LIN PHY : Enable
- CAN PHY : Stand-by Mode Enable
- LIN PHY : Disable

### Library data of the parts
C2 C40 C41 = CMP-0078241-1: CAP, CERM, 0.1 µF, 10 V,+/- 10%, X7R, 0402; Manufacturer: Kemet; TaMin_C: -55°C; Polarized: N; SizeAreaWB_mm2: 3; U/M: EA; Value: 0.1uF; TaMax_C: 125°C; SizeZ_mm: 0.6; SizeX_mm: 1; SizeY_mm: 0.5; Value2: 10V; CompType: Capacitor; Cap_F: 100nF; AEC Category: Q200
R5 R7 R8 R27 R203 R206 = CMP-0025958-3: as R2 on sheet PROC117B_Temp_Current_sensors_EPROM
R6 R33 = CMP-0026938-5: RES, 4.7 k, 5%, 0.063 W, AEC-Q200 Grade 0, 0402; Manufacturer: Vishay-Dale; Power_W: 63mW; TempCo: 200 ppm/C; Value_Code: 4k70; Value: 4.7k; EIA_Code: E24; SizeX_mm: 1; SizeY_mm: 0.5; SizeZ_mm: 0.6; Value2: 0.063W; AEC Qualified: Y; VDC_V: 50V; AEC Category: Q200; AEC Grade: 0
R13 R16 = CMP-0026542-2: RES, 750, 1%, 0.063 W, AEC-Q200 Grade 0, 0402; Manufacturer: Vishay-Dale; Power_W: 63mW; TempCo: 100 ppm/C; Value_Code: 750R; Value: 750; EIA_Code: E96; SizeX_mm: 1; SizeY_mm: 0.5; SizeZ_mm: 0.6; Value2: 0.063W; AEC Qualified: Y; VDC_V: 50V; AEC Grade: 0; AEC Category: Q200
R15 R127 R128 R156 = CMP-0026992-3: RES, 0, 5%, 0.1 W, AEC-Q200 Grade 0, 0402; Manufacturer: Panasonic; Power_W: 100mW; TempCo: 600 ppm/C; Value_Code: 0000; Value: 0; EIA_Code: E24; SizeX_mm: 1; SizeY_mm: 0.5; SizeZ_mm: 0.6; Value2: 0.1W; AEC Qualified: Y; VDC_V: 50V; AEC Category: Q200; SizeAreaWB_mm2: 3
R70 = CMP-0026071-3: RES, 1.00 k, 1%, 0.063 W, AEC-Q200 Grade 0, 0402; Manufacturer: Vishay-Dale; Power_W: 63mW; TempCo: 100 ppm/C; Value_Code: 1k00; Value: 1.00k; EIA_Code: E96; Res_ohm: 1k; SizeX_mm: 1; SizeY_mm: 0.5; SizeZ_mm: 0.6; Value2: 0.063W; AEC Qualified: Y; VDC_V: 50V; AEC Category: Q200; AEC Grade: 0
R204 R207 = CMP-0026557-2: RES, 7.87 k, 1%, 0.063 W, AEC-Q200 Grade 0, 0402; Manufacturer: Vishay-Dale; Power_W: 63mW; TempCo: 100 ppm/C; Value_Code: 7k87; Value: 7.87k; EIA_Code: E96; SizeX_mm: 1; SizeY_mm: 0.5; SizeZ_mm: 0.6; Value2: 0.063W; AEC Qualified: Y; VDC_V: 50V; AEC Grade: 0; AEC Category: Q200
R205 R208 = CMP-0026574-2: RES, 82.5 k, 1%, 0.063 W, AEC-Q200 Grade 0, 0402; Manufacturer: Vishay-Dale; Power_W: 63mW; TempCo: 100 ppm/C; Value_Code: 82k5; Value: 82.5k; EIA_Code: E96; SizeX_mm: 1; SizeY_mm: 0.5; SizeZ_mm: 0.6; Value2: 0.063W; AEC Qualified: Y; VDC_V: 50V; AEC Grade: 0; AEC Category: Q200
S1 = CMP-0002304-1: Switch, SPST, Slide, Off-On, 6 Pos, 0.025A, 24V, SMD; Manufacturer: CTS Electrocomponents; CurrentRating_mA: 25A; PositionCount: 6; SizeX_mm: 8.44; SizeY_mm: 8.79; SizeZ_mm: 2.65; SizeArea_mm2: 74.1876; SizeAreaWB_mm2: 112.6476
S4 = CMP-0002128-3: Switch, Slide, SPST 4 poles, SMT; Manufacturer: CTS Electrocomponents; CurrentRating_mA: 25A; PositionCount: 4; VDC_V: 24V; SwitchFunction: Off-On
TP1 = CMP-0078143-3: TEST POINT.  No entry in BOM.
U4 U24 = CMP-0067415-1: 10-Ohm Quad SPDT Analog Switch, RSV0016A (UQFN-16); Alternate Manufacturer: Texas Instruments; SizeAreaWB_mm2: 10.08; U/M: EA; SizeZ_mm: 0.55; SizeX_mm: 1.8; SizeY_mm: 2.6; SizeArea_mm2: 4.68; CompType: IC
U12 = CMP-0067412-1: 0.45-Ohm Quad SPDT Analog Switch Quad-Channel 2:1 Multiplexer/Demultiplexer with Two Controls, PW0016A (TSSOP-16); Alternate Manufacturer: Texas Instruments; SizeAreaWB_mm2: 58.8; U/M: EA; SizeZ_mm: 1.2; SizeX_mm: 6.4; SizeY_mm: 5.0; SizeArea_mm2: 32.0; CompType: IC

## Sheet PROC117B_XDS110_Interface_1A.SchDoc: XDS110_INTERFACE_1A
size 431 x 279 mm; Date: Not shown in title block; ApprovedBy: Not shown in title block; CheckedBy: Not shown in title block; Author: Not shown in title block; CompanyName: Not shown in title block; DrawnBy: Mistral; Engineer: Mistral; Organization: Not shown in title block; Address1: Not shown in title block; Address2: Not shown in title block; Address3: Not shown in title block; Address4: Not shown in title block; DocumentNumber: 11; Revision: Use project parameter SCH_Rev; SheetNumber: 11; SheetTotal: 16; PageSetup: Record=PageOptions¦CenterHorizontal=True¦CenterVertical=True¦PrintScale=1.00¦XCorrection=1.00¦YCorrection=1.00¦PrintKind=0¦BorderSize=5000000¦LeftOffset=0¦BottomOffset=0¦Orientation=2¦PaperLength=1000¦PaperWidth=1000¦Scale=100¦PaperSource=15¦PrintQuality=600¦MediaType=1¦DitherType=10¦PaperKind=Letter¦PrintScaleMode=1
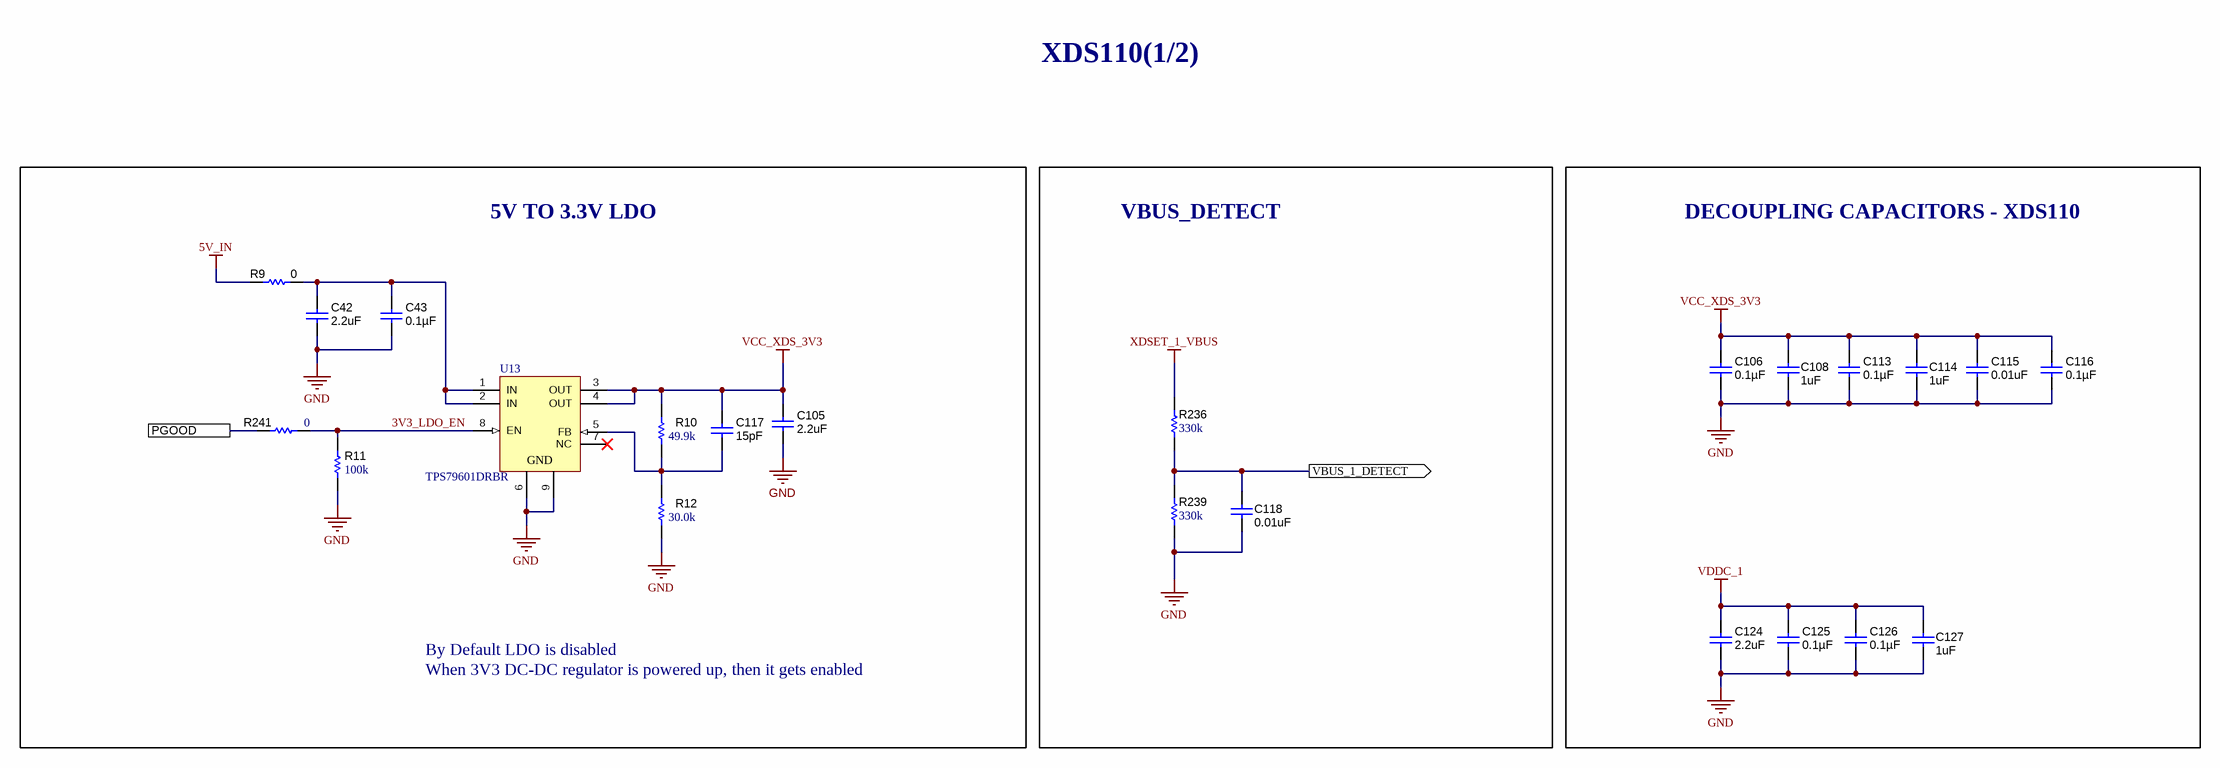
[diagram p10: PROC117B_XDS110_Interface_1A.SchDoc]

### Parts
C42  ValueDisplayed: 2.2uF  [0402_065L]  (hidden comment: C1005X7S1A225K050BC)
C43  ValueDisplayed: 0.1µF  [0402L]  (hidden comment: C0402C104K8RACTU)
C105  ValueDisplayed: 2.2uF  [0402_065L]  (hidden comment: C1005X7S1A225K050BC)
C106  ValueDisplayed: 0.1µF  [0402L]  (hidden comment: C0402C104K8RACTU)
C108  ValueDisplayed: 1uF  [0402L]  (hidden comment: GRT155C81A105KE01D)
C113  ValueDisplayed: 0.1µF  [0402L]  (hidden comment: C0402C104K8RACTU)
C114  ValueDisplayed: 1uF  [0402L]  (hidden comment: GRT155C81A105KE01D)
C115  ValueDisplayed: 0.01uF  [0402L]  (hidden comment: GCM155R71E103KA37D)
C116  ValueDisplayed: 0.1µF  [0402L]  (hidden comment: C0402C104K8RACTU)
C117  ValueDisplayed: 15pF  [0402L]  (hidden comment: 04025A150FAT2A)
C118  ValueDisplayed: 0.01uF  [0402L]  (hidden comment: GCM155R71E103KA37D)
C124  ValueDisplayed: 2.2uF  [0402_065L]  (hidden comment: C1005X7S1A225K050BC)
C125  ValueDisplayed: 0.1µF  [0402L]  (hidden comment: C0402C104K8RACTU)
C126  ValueDisplayed: 0.1µF  [0402L]  (hidden comment: C0402C104K8RACTU)
C127  ValueDisplayed: 1uF  [0402L]  (hidden comment: GRT155C81A105KE01D)
R9  ValueDisplayed: 0  [0603]  (hidden comment: MCT06030Z0000ZP500)
R10  ValueDisplayed: 49.9k  [0402L]  (hidden comment: CRCW040249K9FKED)
R11  ValueDisplayed: 100k  [0402L]  (hidden comment: CRCW0402100KFKED)
R12  ValueDisplayed: 30.0k  [0402L]  (hidden comment: CRCW040230K0FKED)
R236  ValueDisplayed: 330k  [0402L]  (hidden comment: CRCW0402330KFKED)
R239  ValueDisplayed: 330k  [0402L]  (hidden comment: CRCW0402330KFKED)
R241  ValueDisplayed: 0  [0402]  (hidden comment: ERJ-2GE0R00X)
U13  TPS79601DRBR  [DRB0008B]

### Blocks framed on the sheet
5V TO 3.3V LDO: C42 C43 C105 C117 R9-R12 R241 U13
VBUS_DETECT: C118 R236 R239
DECOUPLING CAPACITORS - XDS110: C106 C108 C113-C116 C124-C127

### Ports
PGOOD, VBUS_1_DETECT (out)

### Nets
5V_IN: R9.1
GND: C42.2 C43.2 C105.1 C106.1 C108.2 C113.1 C114.2 C115.2 C116.1 C118.1 C124.1 C125.1 C126.1 C127.2 R11.1 R12.1 R239.1 U13.6(GND) U13.9(GND)
VCC_XDS_3V3: C105.2 C106.2 C108.1 C113.2 C114.1 C115.1 C116.2 C117.2 R10.2 U13.3(OUT) U13.4(OUT)
VDDC_1: C124.2 C125.2 C126.2 C127.1
XDSET_1_VBUS: R236.2
3V3_LDO_EN: R11.2 R241.2 U13.8(EN)
PGOOD: R241.1 ; port PGOOD
VBUS_1_DETECT: C118.2 R236.1 R239.2 ; port VBUS_1_DETECT
NetC42_1: C42.1 C43.1 R9.2 U13.1(IN) U13.2(IN)
NetC117_1: C117.1 R10.1 R12.2 U13.5(FB)

Not connected (* = marked no-connect by the designer): U13 7(NC)*

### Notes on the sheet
- XDS110(1/2)
- By Default LDO is disabled
- When 3V3 DC-DC regulator is powered up, then it gets enabled

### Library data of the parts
C42 C105 C124 = CMP-0006302-2: CAP, CERM, 2.2 uF, 10 V, +/- 10%, X7S, 0402; Manufacturer: TDK; TaMin_C: -55°C; ESR_ohm: 5.925m; Polarized: N; SizeAreaWB_mm2: 3; Value1: 0.005925 ohm; U/M: EA; Value: 2.2uF; TaMax_C: 125°C; SizeZ_mm: 0.65; SizeX_mm: 1; SizeY_mm: 0.5; Cap_Case: 0402_065; Value2: 10V; CompType: Capacitor; Cap_F: 2.2µF; IRMS_A: 2.05591A; AEC Category: Q200
C43 = CMP-0078241-1: CAP, CERM, 0.1 µF, 10 V,+/- 10%, X7R, 0402; Manufacturer: Kemet; TaMin_C: -55°C; Polarized: N; SizeAreaWB_mm2: 3; U/M: EA; Value: 0.1uF; TaMax_C: 125°C; SizeZ_mm: 0.6; SizeX_mm: 1; SizeY_mm: 0.5; Cap_Case: 0402; Value2: 10V; Cap_F: 100nF; AEC Category: Q200
C106 C113 C116 C125 C126 = CMP-0078241-1: CAP, CERM, 0.1 µF, 10 V,+/- 10%, X7R, 0402; Manufacturer: Kemet; TaMin_C: -55°C; Polarized: N; SizeAreaWB_mm2: 3; U/M: EA; Value: 0.1uF; TaMax_C: 125°C; SizeZ_mm: 0.6; SizeX_mm: 1; SizeY_mm: 0.5; Cap_Case: 0402; Value2: 10V; CompType: Capacitor; Cap_F: 100nF; AEC Category: Q200
C108 C114 C127 = CMP-0006272-2: CAP, CERM, 1 uF, 10 V, +/- 10%, X6S, 0402; Manufacturer: TDK; Polarized: N; Value: 1uF; U/M: EA; Cap_F: 1µF; Value1: Unknown; VDC_V: 16V; TempCo: X5R; TaMin_C: -55°C; TaMax_C: 85°C; Cap_Case: 0402; SizeArea_mm2: 0.5; SizeAreaWB_mm2: 3; SizeX_mm: 1; SizeZ_mm: 0.6; AEC Category: Q200
C115 C118 = CMP-0006352-2: as C88 on sheet PROC117B_QSPI_Flash_LVDS_Driver
C117 = CMP-0078217-1: CAP, CERM, 15 pF, 50 V,+/- 1%, C0G/NP0, 0402; Manufacturer: AVX; TaMin_C: -55°C; Polarized: N; Green_Lifecycle: Not Set; SizeAreaWB_mm2: 3; Green_REACh: Incomplete; U/M: EA; Value: 15pF; TaMax_C: 125°C; SizeZ_mm: 0.6; SizeX_mm: 1; SizeY_mm: 0.5; Cap_Case: 0402; Value2: 50V; AEC Category: Q200
R9 = CMP-0025884-3: RES, 0, 5%, 0.125 W, 0603; Manufacturer: Vishay/Beyschlag; Power_W: 125mW; TempCo: ppm/C; Value_Code: 0000; U/M: EA; Value: 0; EIA_Code: E24; SizeX_mm: 1.6; SizeY_mm: 0.8; SizeZ_mm: 1; Value2: 0.125W; SizeArea_mm2: 1.28; AEC Qualified: N; AEC Category: Q200
R10 = CMP-0026403-2: RES, 49.9 k, 1%, 0.063 W, AEC-Q200 Grade 0, 0402; Manufacturer: Vishay-Dale; Power_W: 63mW; TempCo: 100 ppm/C; Value_Code: 49k9; Value: 49.9k; EIA_Code: E96; SizeX_mm: 1; SizeY_mm: 0.5; SizeZ_mm: 0.6; Value2: 0.063W; AEC Qualified: Y; VDC_V: 50V; AEC Category: Q200; AEC Grade: 0
R11 = CMP-0025950-3: RES, 100 k, 1%, 0.063 W, AEC-Q200 Grade 0, 0402; Manufacturer: Vishay-Dale; Power_W: 63mW; TempCo: 100 ppm/C; Value: 100k; EIA_Code: E96; SizeX_mm: 1; SizeY_mm: 0.5; SizeZ_mm: 0.6; Value2: 0.063W; AEC Qualified: Y; VDC_V: 50V; AEC Category: Q200; AEC Grade: 0
R12 = CMP-0078244-2: RES, 30.0 k, 1%, 0.063 W, AEC-Q200 Grade 0, 0402; Manufacturer: Vishay-Dale; Power_W: 63mW; Green_Lifecycle: Active; TempCo: 100 ppm/C; Value_Code: 30k0; Green_REACh: Passed; Value: 30.0k; Res_ohm: 30k; SizeX_mm: 1; SizeY_mm: 0.5; SizeZ_mm: 0.6; Value2: 0.063W; AEC Qualified: Y; VDC_V: 50V; AEC Grade: 0; AEC Category: Q200
R236 R239 = CMP-0078210-2: RES, 330 k, 1%, 0.063 W, AEC-Q200 Grade 0, 0402; Manufacturer: Vishay-Dale; SizeArea_mm2: 0.5; AEC Qualified: Y; AEC Category: Q200; Value: 330k; SizeZ_mm: 0.6; TempCo: 100 ppm/C; AEC Grade: 0; Power_W: 63mW; VDC_V: 50V; Value2: 0.063W; SizeX_mm: 1
R241 = CMP-0026992-3: RES, 0, 5%, 0.1 W, AEC-Q200 Grade 0, 0402; Manufacturer: Panasonic; Power_W: 100mW; TempCo: 600 ppm/C; Value_Code: 0000; Value: 0; EIA_Code: E24; SizeX_mm: 1; SizeY_mm: 0.5; SizeZ_mm: 0.6; Value2: 0.1W; CompType: Resistor; AEC Qualified: Y; VDC_V: 50V; AEC Category: Q200; SizeAreaWB_mm2: 3; INSTALLATION: DNP
U13 = CMP-0036402-3: Single Output High PSRR LDO, 1 A, Adjustable 1.2 to 5.5 V Output, 2.7 to 5.5 V Input, 8-pin SON (DRB), -40 to 125 degC, Green (RoHS & no Sb/Br); Manufacturer: Texas Instruments; Vin(Min)(V): 2.7; Vout Adj(Max)(V): 5.5; Vout Adj(Min)(V): 1.2; Accuracy(%): 2; SubFamily: Single Channel LDO; Iq(Typ)(mA): 0.26; Vdo(Typ)(mV): 250; Iout(Max)(A): 1; AEC Category: Q200; AEC Qualified: N; CompType: IC; SizeAreaWB_mm2: 16.0; SizeArea_mm2: 9.0; SizeX_mm: 3.0; SizeZ_mm: 1.0

## Sheet PROC117B_XDS110_Interface_1B.SchDoc: XDS110_INTERFACE_1B
size 431 x 279 mm; Date: Not shown in title block; ApprovedBy: Not shown in title block; CheckedBy: Not shown in title block; Author: Not shown in title block; CompanyName: Not shown in title block; DrawnBy: Mistral; Engineer: Not shown in title block; Organization: Not shown in title block; Address1: Not shown in title block; Address2: Not shown in title block; Address3: Not shown in title block; Address4: Not shown in title block; DocumentNumber: 12; Revision: Use project parameter SCH_Rev; SheetNumber: 12; SheetTotal: 16; PageSetup: Record=PageOptions¦CenterHorizontal=True¦CenterVertical=True¦PrintScale=1.00¦XCorrection=1.00¦YCorrection=1.00¦PrintKind=0¦BorderSize=5000000¦LeftOffset=0¦BottomOffset=0¦Orientation=2¦PaperLength=1000¦PaperWidth=1000¦Scale=100¦PaperSource=15¦PrintQuality=600¦MediaType=1¦DitherType=10¦PaperKind=Letter¦PrintScaleMode=1
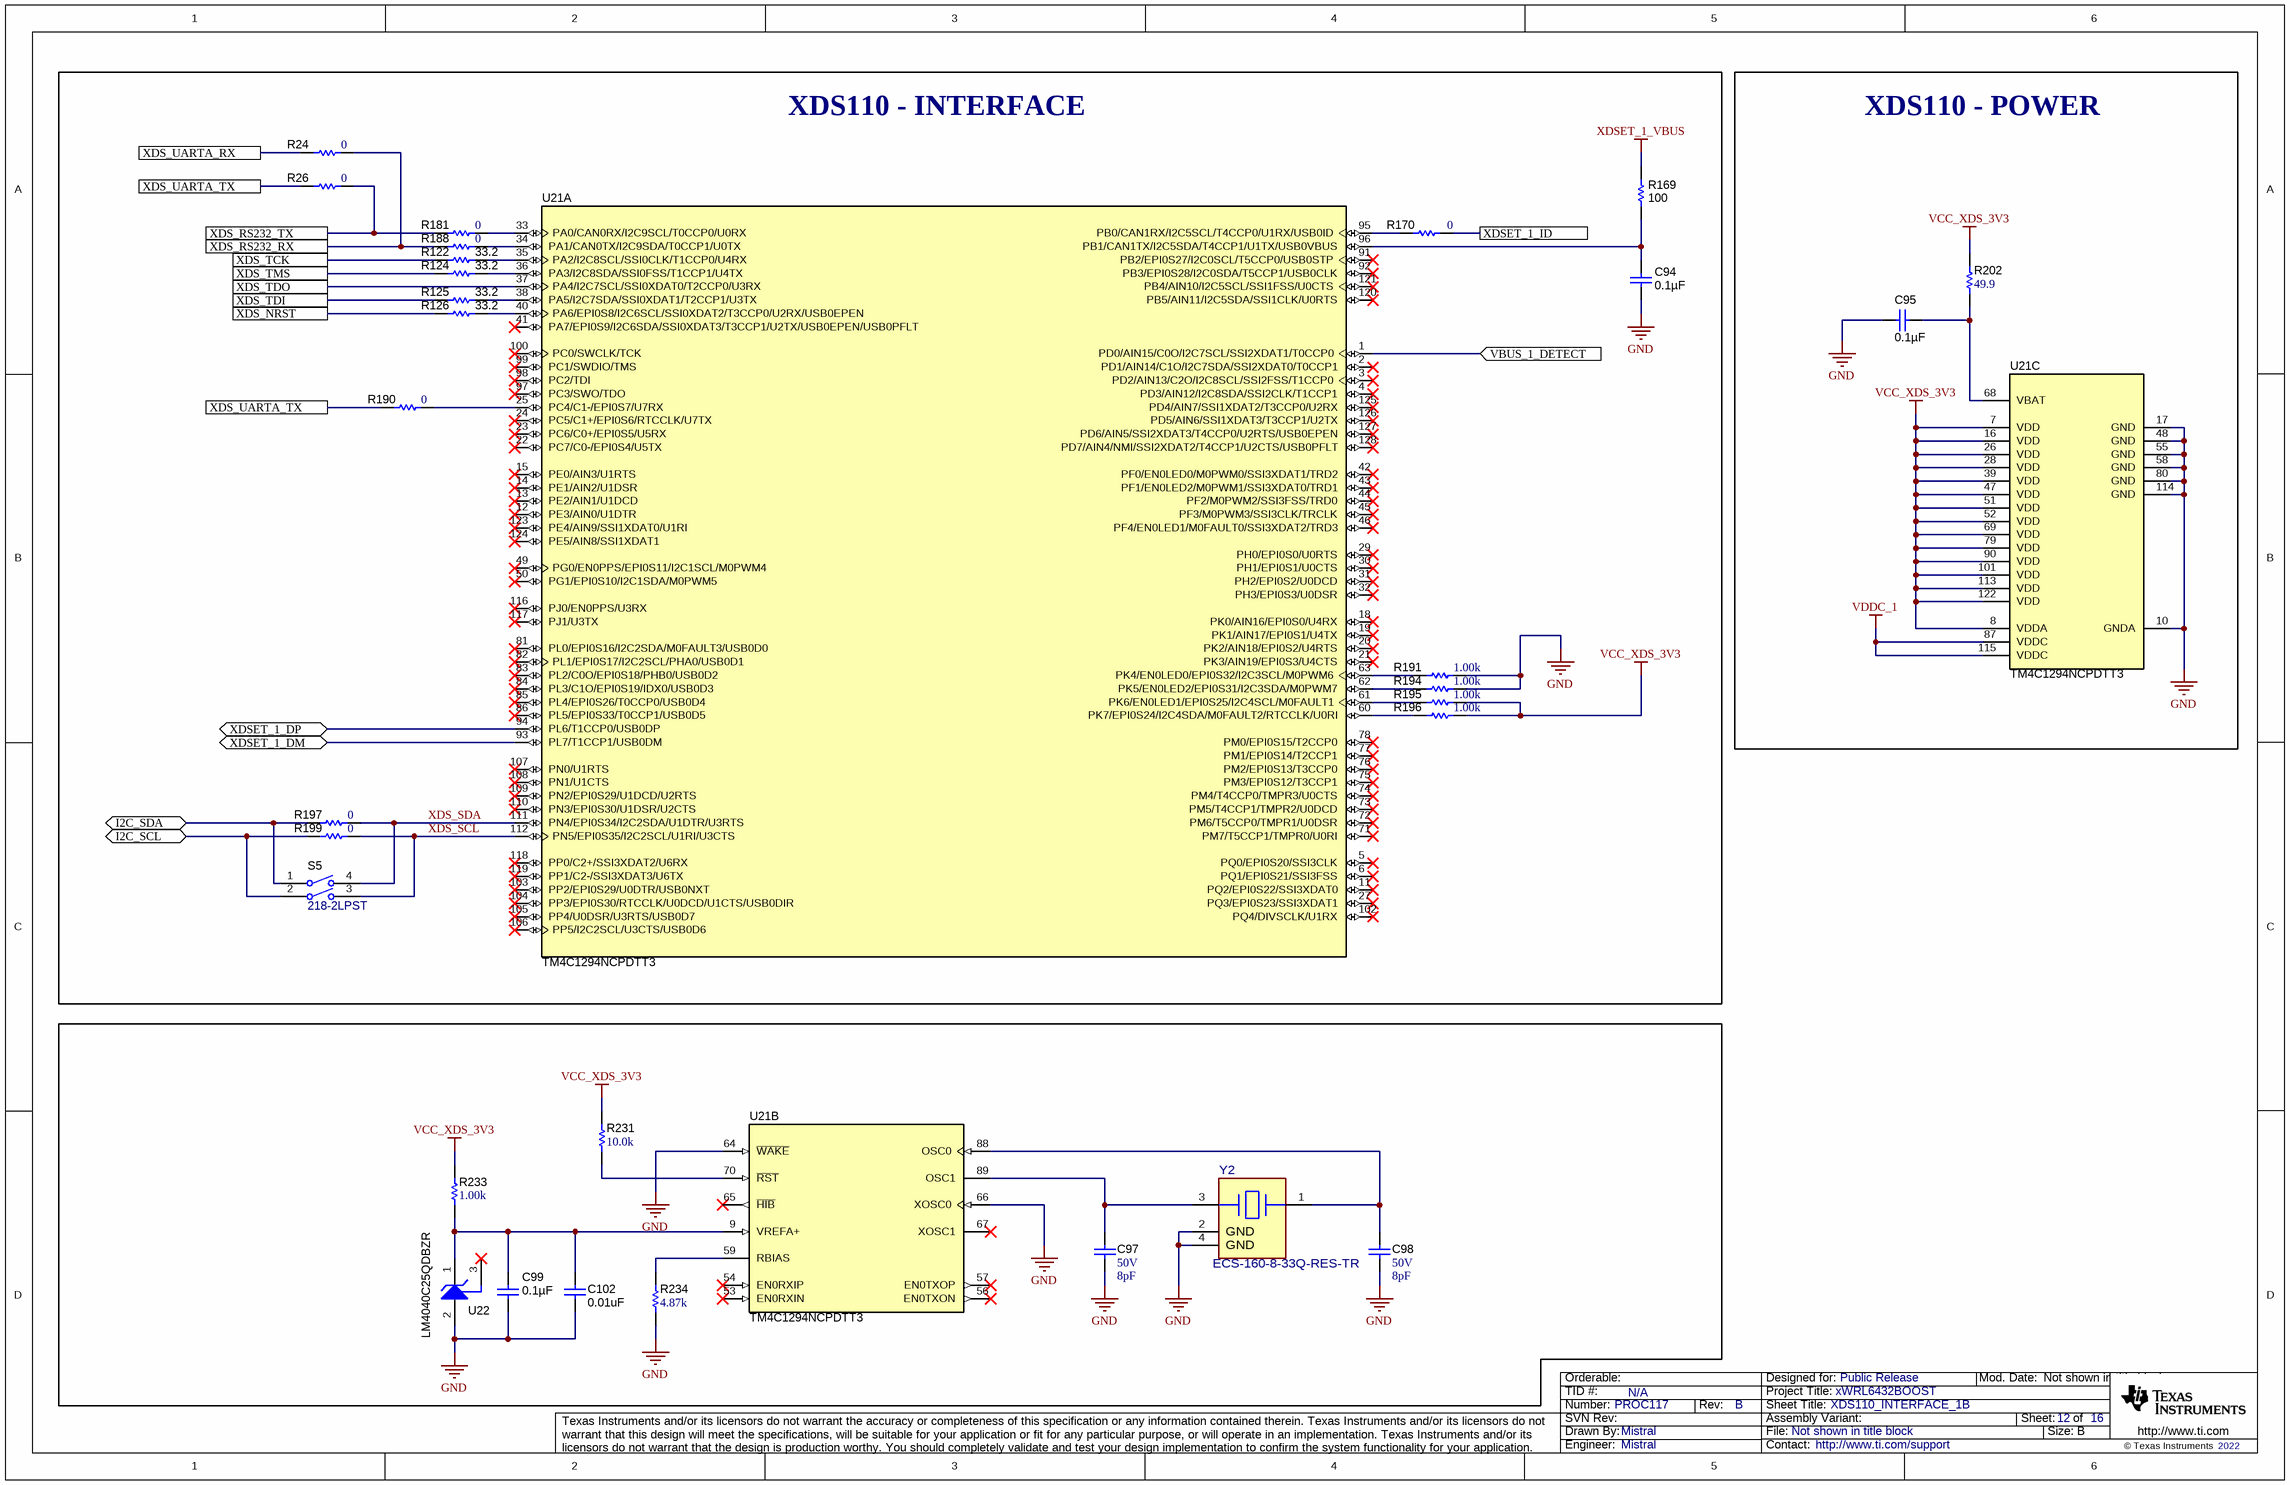
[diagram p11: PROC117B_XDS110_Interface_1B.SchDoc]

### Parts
C94  ValueDisplayed: 0.1µF  [0402L]  (hidden comment: C0402C104K8RACTU)
C95  ValueDisplayed: 0.1µF  [0402L]  (hidden comment: C0402C104K8RACTU)
C97  VDC_V: 50V  ValueDisplayed: 8pF  [0402L]  (hidden comment: CC0402DRNPO9BN8R0)
C98  VDC_V: 50V  ValueDisplayed: 8pF  [0402L]  (hidden comment: CC0402DRNPO9BN8R0)
C99  ValueDisplayed: 0.1µF  [0402L]  (hidden comment: C0402C104K8RACTU)
C102  ValueDisplayed: 0.01uF  [0402L]  (hidden comment: GCM155R71E103KA37D)
R24  ValueDisplayed: 0  [0402]  (hidden comment: ERJ-2GE0R00X)
R26  ValueDisplayed: 0  [0402]  (hidden comment: ERJ-2GE0R00X)
R122  ValueDisplayed: 33.2  [0201_Silk]  (hidden comment: CRCW020133R2FNED)
R124  ValueDisplayed: 33.2  [0201_Silk]  (hidden comment: CRCW020133R2FNED)
R125  ValueDisplayed: 33.2  [0201_Silk]  (hidden comment: CRCW020133R2FNED)
R126  ValueDisplayed: 33.2  [0201_Silk]  (hidden comment: CRCW020133R2FNED)
R169  ValueDisplayed: 100  [0402L]  (hidden comment: ERJ-2GEJ101X)
R170  ValueDisplayed: 0  [0402]  (hidden comment: ERJ-2GE0R00X)
R181  ValueDisplayed: 0  [0402]  (hidden comment: ERJ-2GE0R00X)
R188  ValueDisplayed: 0  [0402]  (hidden comment: ERJ-2GE0R00X)
R190  ValueDisplayed: 0  [0201_Silk]  (hidden comment: CRCW02010000Z0ED)
R191  ValueDisplayed: 1.00k  [0402L]  (hidden comment: CRCW04021K00FKED)
R194  ValueDisplayed: 1.00k  [0402L]  (hidden comment: CRCW04021K00FKED)
R195  ValueDisplayed: 1.00k  [0402L]  (hidden comment: CRCW04021K00FKED)
R196  ValueDisplayed: 1.00k  [0402L]  (hidden comment: CRCW04021K00FKED)
R197  ValueDisplayed: 0  [0402]  (hidden comment: ERJ-2GE0R00X)
R199  ValueDisplayed: 0  [0402]  (hidden comment: ERJ-2GE0R00X)
R202  ValueDisplayed: 49.9  [0402L]  (hidden comment: CRCW040249R9FKED)
R231  ValueDisplayed: 10.0k  [0402L]  (hidden comment: CRCW040210K0FKED)
R233  ValueDisplayed: 1.00k  [0402L]  (hidden comment: CRCW04021K00FKED)
R234  ValueDisplayed: 4.87k  [0402L]  (hidden comment: CRCW04024K87FKED)
S5  218-2LPST  [SW_218-2LP]
U21  TM4C1294NCPDTT3  [PDT0128A]  (parts A,B,C of 3)
U22  LM4040C25QDBZR  [DBZ0003A_N]
Y2  ECS-160-8-33Q-RES-TR  [FP-ECS-160-8-33Q-RES-TR_SMT4_3MM2_2MM5-MFG]

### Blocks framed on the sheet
XDS110 - INTERFACE: C94 R24 R26 R122 R124-R126 R169 R170 R181 R188 R190 R191 R194-R197 R199 S5 U21
XDS110 - POWER: C95 R202 U21

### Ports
I2C_SCL (bidir), I2C_SDA (bidir), VBUS_1_DETECT (in), XDS_NRST, XDS_RS232_RX, XDS_RS232_TX, XDS_TCK, XDS_TDI, XDS_TDO, XDS_TMS, XDS_UARTA_RX, XDS_UARTA_TX, XDSET_1_DM (bidir), XDSET_1_DP (bidir), XDSET_1_ID

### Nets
GND: C94.2 C95.1 C97.1 C98.1 C99.1 C102.1 R191.2 R194.2 R234.1 U21.10(GNDA) U21.17(GND) U21.48(GND) U21.55(GND) U21.58(GND) U21.64(~{WAKE}) U21.66(XOSC0) U21.80(GND) U21.114(GND) U22.2(ANODE) Y2.2(GND) Y2.4(GND)
VCC_XDS_3V3: R195.2 R196.2 R202.1 R231.2 R233.2 U21.7(VDD) U21.8(VDDA) U21.16(VDD) U21.26(VDD) U21.28(VDD) U21.39(VDD) U21.47(VDD) U21.51(VDD) U21.52(VDD) U21.69(VDD) U21.79(VDD) U21.90(VDD) U21.101(VDD) U21.113(VDD) U21.122(VDD)
VDDC_1: U21.87(VDDC) U21.115(VDDC)
XDSET_1_VBUS: R169.2
I2C_SCL: R199.1 S5.2 ; port I2C_SCL
I2C_SDA: R197.1 S5.1 ; port I2C_SDA
VBUS_1_DETECT: U21.1(PD0/AIN15/C0O/I2C7SCL/SSI2XDAT1/T0CCP0) ; port VBUS_1_DETECT
XDS_NRST: R126.2 ; port XDS_NRST
XDS_RS232_RX: R24.2 R188.1 ; port XDS_RS232_RX
XDS_RS232_TX: R26.2 R181.1 ; port XDS_RS232_TX
XDS_SCL: R199.2 S5.3 U21.112(PN5/EPI0S35/I2C2SCL/U1RI/U3CTS)
XDS_SDA: R197.2 S5.4 U21.111(PN4/EPI0S34/I2C2SDA/U1DTR/U3RTS)
XDS_TCK: R122.2 ; port XDS_TCK
XDS_TDI: R125.2 ; port XDS_TDI
XDS_TDO: U21.37(PA4/I2C7SCL/SSI0XDAT0/T2CCP0/U3RX) ; port XDS_TDO
XDS_TMS: R124.2 ; port XDS_TMS
XDS_UARTA_RX: R24.1 ; port XDS_UARTA_RX
XDS_UARTA_TX: R26.1 R190.1 ; port XDS_UARTA_TX
XDSET_1_DM: U21.93(PL7/T1CCP1/USB0DM) ; port XDSET_1_DM
XDSET_1_DP: U21.94(PL6/T1CCP0/USB0DP) ; port XDSET_1_DP
XDSET_1_ID: R170.2 ; port XDSET_1_ID
NetC94_1: C94.1 R169.1 U21.96(PB1/CAN1TX/I2C5SDA/T4CCP1/U1TX/USB0VBUS)
NetC95_2: C95.2 R202.2 U21.68(VBAT)
NetC97_2: C97.2 U21.89(OSC1) Y2.3(OUT/IN)
NetC98_2: C98.2 U21.88(OSC0) Y2.1(IN/OUT)
NetC99_2: C99.2 C102.2 R233.1 U21.9(VREFA+) U22.1(CATHODE)
NetR122_1: R122.1 U21.35(PA2/I2C8SCL/SSI0CLK/T1CCP0/U4RX)
NetR124_1: R124.1 U21.36(PA3/I2C8SDA/SSI0FSS/T1CCP1/U4TX)
NetR125_1: R125.1 U21.38(PA5/I2C7SDA/SSI0XDAT1/T2CCP1/U3TX)
NetR126_1: R126.1 U21.40(PA6/EPI0S8/I2C6SCL/SSI0XDAT2/T3CCP0/U2RX/USB0EPEN)
NetR170_1: R170.1 U21.95(PB0/CAN1RX/I2C5SCL/T4CCP0/U1RX/USB0ID)
NetR181_2: R181.2 U21.33(PA0/CAN0RX/I2C9SCL/T0CCP0/U0RX)
NetR188_2: R188.2 U21.34(PA1/CAN0TX/I2C9SDA/T0CCP1/U0TX)
NetR190_2: R190.2 U21.25(PC4/C1-/EPI0S7/U7RX)
NetR191_1: R191.1 U21.63(PK4/EN0LED0/EPI0S32/I2C3SCL/M0PWM6)
NetR194_1: R194.1 U21.62(PK5/EN0LED2/EPI0S31/I2C3SDA/M0PWM7)
NetR195_1: R195.1 U21.61(PK6/EN0LED1/EPI0S25/I2C4SCL/M0FAULT1)
NetR196_1: R196.1 U21.60(PK7/EPI0S24/I2C4SDA/M0FAULT2/RTCCLK/U0RI)
NetR231_1: R231.1 U21.70(~{RST})
NetR234_2: R234.2 U21.59(RBIAS)

Not connected (* = marked no-connect by the designer): U21 2(PD1/AIN14/C1O/I2C7SDA/SSI2XDAT0/T0CCP1)* 3(PD2/AIN13/C2O/I2C8SCL/SSI2FSS/T1CCP0)* 4(PD3/AIN12/I2C8SDA/SSI2CLK/T1CCP1)* 5(PQ0/EPI0S20/SSI3CLK)* 6(PQ1/EPI0S21/SSI3FSS)* 11(PQ2/EPI0S22/SSI3XDAT0)* 12(PE3/AIN0/U1DTR)* 13(PE2/AIN1/U1DCD)* 14(PE1/AIN2/U1DSR)* 15(PE0/AIN3/U1RTS)* 18(PK0/AIN16/EPI0S0/U4RX)* 19(PK1/AIN17/EPI0S1/U4TX)* 20(PK2/AIN18/EPI0S2/U4RTS)* 21(PK3/AIN19/EPI0S3/U4CTS)* 22(PC7/C0-/EPI0S4/U5TX)* 23(PC6/C0+/EPI0S5/U5RX)* 24(PC5/C1+/EPI0S6/RTCCLK/U7TX)* 27(PQ3/EPI0S23/SSI3XDAT1)* 29(PH0/EPI0S0/U0RTS)* 30(PH1/EPI0S1/U0CTS)* 31(PH2/EPI0S2/U0DCD)* 32(PH3/EPI0S3/U0DSR)* 41(PA7/EPI0S9/I2C6SDA/SSI0XDAT3/T3CCP1/U2TX/USB0EPEN/USB0PFLT)* 42(PF0/EN0LED0/M0PWM0/SSI3XDAT1/TRD2)* 43(PF1/EN0LED2/M0PWM1/SSI3XDAT0/TRD1)* 44(PF2/M0PWM2/SSI3FSS/TRD0)* 45(PF3/M0PWM3/SSI3CLK/TRCLK)* 46(PF4/EN0LED1/M0FAULT0/SSI3XDAT2/TRD3)* 49(PG0/EN0PPS/EPI0S11/I2C1SCL/M0PWM4)* 50(PG1/EPI0S10/I2C1SDA/M0PWM5)* 53(EN0RXIN)* 54(EN0RXIP)* 56(EN0TXON)* 57(EN0TXOP)* 65(~{HIB})* 67(XOSC1)* 71(PM7/T5CCP1/TMPR0/U0RI)* 72(PM6/T5CCP0/TMPR1/U0DSR)* 73(PM5/T4CCP1/TMPR2/U0DCD)* 74(PM4/T4CCP0/TMPR3/U0CTS)* 75(PM3/EPI0S12/T3CCP1)* 76(PM2/EPI0S13/T3CCP0)* 77(PM1/EPI0S14/T2CCP1)* 78(PM0/EPI0S15/T2CCP0)* 81(PL0/EPI0S16/I2C2SDA/M0FAULT3/USB0D0)* 82(PL1/EPI0S17/I2C2SCL/PHA0/USB0D1)* 83(PL2/C0O/EPI0S18/PHB0/USB0D2)* 84(PL3/C1O/EPI0S19/IDX0/USB0D3)* 85(PL4/EPI0S26/T0CCP0/USB0D4)* 86(PL5/EPI0S33/T0CCP1/USB0D5)* 91(PB2/EPI0S27/I2C0SCL/T5CCP0/USB0STP)* 92(PB3/EPI0S28/I2C0SDA/T5CCP1/USB0CLK)* 97(PC3/SWO/TDO)* 98(PC2/TDI)* 99(PC1/SWDIO/TMS)* 100(PC0/SWCLK/TCK)* 102(PQ4/DIVSCLK/U1RX)* 103(PP2/EPI0S29/U0DTR/USB0NXT)* 104(PP3/EPI0S30/RTCCLK/U0DCD/U1CTS/USB0DIR)* 105(PP4/U0DSR/U3RTS/USB0D7)* 106(PP5/I2C2SCL/U3CTS/USB0D6)* 107(PN0/U1RTS)* 108(PN1/U1CTS)* 109(PN2/EPI0S29/U1DCD/U2RTS)* 110(PN3/EPI0S30/U1DSR/U2CTS)* 116(PJ0/EN0PPS/U3RX)* 117(PJ1/U3TX)* 118(PP0/C2+/SSI3XDAT2/U6RX)* 119(PP1/C2-/SSI3XDAT3/U6TX)* 120(PB5/AIN11/I2C5SDA/SSI1CLK/U0RTS)* 121(PB4/AIN10/I2C5SCL/SSI1FSS/U0CTS)* 123(PE4/AIN9/SSI1XDAT0/U1RI)* 124(PE5/AIN8/SSI1XDAT1)* 125(PD4/AIN7/SSI1XDAT2/T3CCP0/U2RX)* 126(PD5/AIN6/SSI1XDAT3/T3CCP1/U2TX)* 127(PD6/AIN5/SSI2XDAT3/T4CCP0/U2RTS/USB0EPEN)* 128(PD7/AIN4/NMI/SSI2XDAT2/T4CCP1/U2CTS/USB0PFLT)*; U22 3(NC)*

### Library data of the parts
C94 C95 C99 = CMP-0078241-1: as C106 on sheet PROC117B_XDS110_Interface_1A
C97 C98 = CMP-0860185-1: CAP, CERM, 8 pF, 50 V,+/- 6.25%, C0G/NP0, 0402; Manufacturer: Yageo; Cap_Case: 0402; Polarized: N; TaMax_C: 125°C; SizeY_mm: 0.5; SizeX_mm: 1; Value: 8pF; AEC Category: Q200; U/M: EA; SizeAreaWB_mm2: 3; TaMin_C: -55°C; SizeZ_mm: 0.6
C102 = CMP-0006352-2: as C88 on sheet PROC117B_QSPI_Flash_LVDS_Driver
R24 R26 R181 R188 R197 R199 = CMP-0026992-3: as R15 on sheet PROC117B_Analog_Mux_SOP_Ctrl
R122 R124-R126 = CMP-0027275-3: as R45-R48 on sheet PROC117B_QSPI_Flash_LVDS_Driver
R169 = CMP-0026993-2: RES, 100, 5%, 0.1 W, AEC-Q200 Grade 0, 0402; Manufacturer: Panasonic; Power_W: 100mW; TempCo: 200 ppm/C; Value_Code: 100R; U/M: EA; Value: 100; EIA_Code: E24; SizeX_mm: 1; SizeY_mm: 0.5; SizeZ_mm: 0.6; Value2: 0.1W; AEC Qualified: Y; AEC Grade: 0; AEC Category: Q200
R170 = CMP-0026992-3: as R241 on sheet PROC117B_XDS110_Interface_1A
R190 = CMP-0027008-4: as R25 on sheet PROC117B_Temp_Current_sensors_EPROM
R191 R194-R196 R233 = CMP-0026071-3: as R70 on sheet PROC117B_Analog_Mux_SOP_Ctrl
R202 = CMP-0026404-2: RES, 49.9, 1%, 0.063 W, AEC-Q200 Grade 0, 0402; Manufacturer: Vishay-Dale; Power_W: 63mW; TempCo: 100 ppm/C; Value_Code: 49R9; Value: 49.9; EIA_Code: E96; SizeX_mm: 1; SizeY_mm: 0.5; SizeZ_mm: 0.6; Value2: 0.063W; AEC Qualified: Y; VDC_V: 50V; AEC Category: Q200; AEC Grade: 0
R231 = CMP-0025958-3: as R2 on sheet PROC117B_Temp_Current_sensors_EPROM
R234 = CMP-0026413-2: RES, 4.87 k, 1%, 0.063 W, AEC-Q200 Grade 0, 0402; Manufacturer: Vishay-Dale; Power_W: 63mW; TempCo: 100 ppm/C; Value_Code: 4k87; Value: 4.87k; EIA_Code: E96; SizeX_mm: 1; SizeY_mm: 0.5; SizeZ_mm: 0.6; Value2: 0.063W; AEC Qualified: Y; VDC_V: 50V; AEC Category: Q200; AEC Grade: 0
S5 = CMP-0002230-1: Switch, SPST, 2 Pos, 25mA, 24VDC, SMD; Manufacturer: CTS Electrocomponents; CurrentRating_mA: 25A; PositionCount: 2; VDC_V: 24V; SwitchFunction: Off-On
U21 = CMP-0029856-2: Tiva C Series Microcontroller, 1024 KB Flash, 256 KB SRAM, 12 Bit, 20 Channels, -40 to 105 degC, 128-Pin TQFP (PDT), Green (RoHS & no Sb/Br), Tray; Manufacturer: Texas Instruments; ADC Channels: 20; CPU: ARM Cortex-M4; Flash: 1024 KB; ADC Resolution: 12 Bits; Max Speed: 120 MHz; SRAM: 256 KB; SizeAreaWB_mm2: 324.0; SizeArea_mm2: 256.0; SizeX_mm: 16.0; SizeZ_mm: 1.2; CompType: IC
U22 = CMP-0033001-1: Precision Micropower Shunt Voltage Reference, 0.5% accuracy, 2.5 V, 15 ppm / degC, 15 mA, -40 to 125 degC, 3-pin SOT-23 (DBZ), Green (RoHS & no Sb/Br); Manufacturer: Texas Instruments; Initial Accuracy @ 25/deg C(%): 0.5; Temp Coeff(Typ)(ppm/ degree C): 15; Temp Coeff(Max)(ppm/ degree C): 100; Rating: Catalog; Min Iz for Regulation(uA): 75; VO(V): 2.5
Y2 = CMP-0095014-1: 16 MHz ±15ppm Crystal 8pF 80 Ohms 4-SMD, No Lead; Manufacturer: ECS; Frequency Stability: 50ppm; SizeZ_mm: 0.8mm; Frequency_Fixed: 16MHz; AEC Qualified: Yes; Esr: 80; AEC Grade: Grade 1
